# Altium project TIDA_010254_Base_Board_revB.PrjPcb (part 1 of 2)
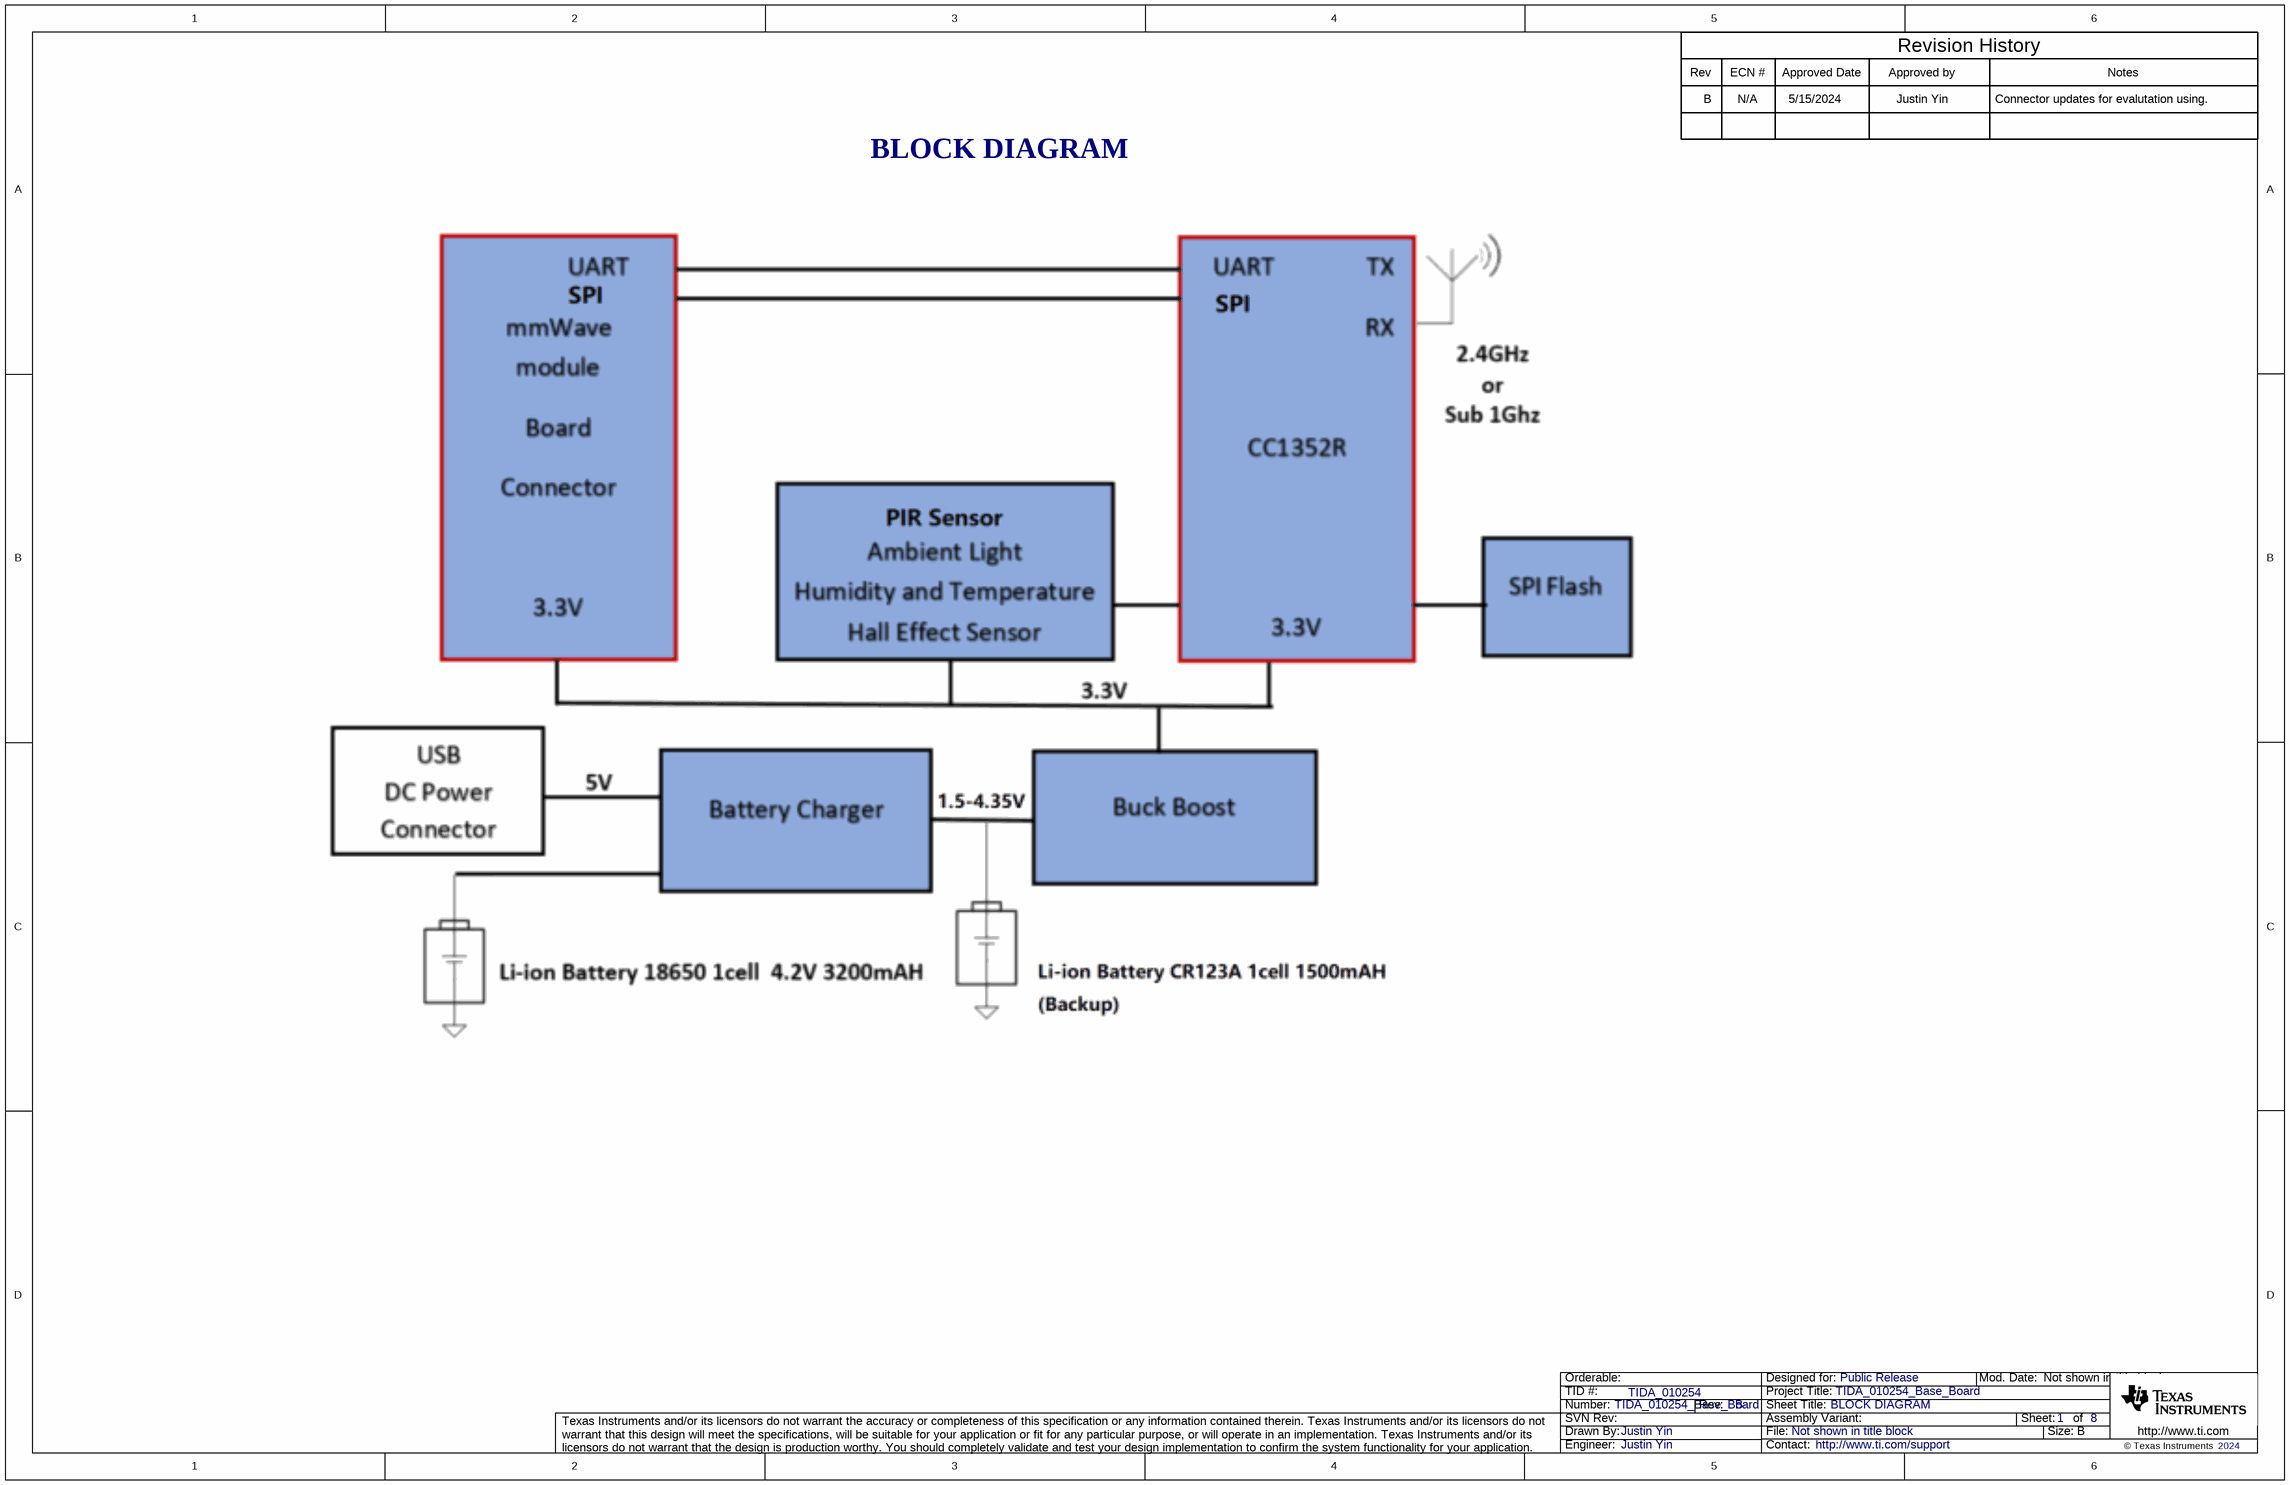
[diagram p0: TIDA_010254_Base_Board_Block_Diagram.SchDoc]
CopyrightYear: 2024; PCB_Layout: Justin Yin; PCB_Rev: B; PRJ_Customer: Public Release; PRJ_Engineer: Justin Yin; PRJ_Number: TIDA_010254_Base_Board; PRJ_Title: TIDA_010254_Base_Board; SCH_Rev: B; TechSupport: http://www.ti.com/support; TID: TIDA_010254
8 sheets, 220 parts. Net scope: flat (ports and power ports of the same name join across sheets).
Board file: TIDA_010254_Base_Board_PCB.PcbDoc
Sheets:
  TIDA_010254_Base_Board_Block_Diagram.SchDoc
  TIDA_010254_Base_Board_Table_Of_Contents.SchDoc
  TIDA_010254_Base_Board_Connector.SchDoc
  TIDA_010254_Base_Board_Charger.SchDoc
  TIDA_010254_Base_Board_DC_Regulators.SchDoc
  TIDA_010254_Base_Board_CC1352R.SchDoc
  TIDA_010254_Base_Board_Sensors.SchDoc
  TIDA_010254_Base_Board_Hardware.SchDoc

## Sheet TIDA_010254_Base_Board_Block_Diagram.SchDoc: BLOCK DIAGRAM
size 431 x 279 mm; Date: Not shown in title block; ApprovedBy: Not shown in title block; CheckedBy: Not shown in title block; Author: Not shown in title block; CompanyName: Not shown in title block; DrawnBy: Justin Yin; Organization: Not shown in title block; Address1: Not shown in title block; Address2: Not shown in title block; Address3: Not shown in title block; Address4: Not shown in title block; DocumentNumber: 1; Revision: Use project parameter SCH_Rev; SheetNumber: 1; SheetTotal: 8; PageSetup: Record=PageOptions¦CenterHorizontal=True¦CenterVertical=True¦PrintScale=1.00¦XCorrection=1.00¦YCorrection=1.00¦PrintKind=0¦BorderSize=5000000¦LeftOffset=0¦BottomOffset=0¦Orientation=2¦PaperLength=1000¦PaperWidth=1000¦Scale=100¦PaperSource=15¦PrintQuality=600¦MediaType=1¦DitherType=10¦PaperKind=Letter¦PrintScaleMode=1

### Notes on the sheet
- Rev
- B
- ECN #
- N/A
- 5/15/2024
- Approved Date
- Approved by
- Justin Yin
- Revision History
- Connector updates for evalutation using.
- Notes
- BLOCK DIAGRAM

## Sheet TIDA_010254_Base_Board_Table_Of_Contents.SchDoc: TABLE OF CONTENTS
size 431 x 279 mm; Date: Not shown in title block; ApprovedBy: Not shown in title block; CheckedBy: Not shown in title block; Author: Not shown in title block; CompanyName: Not shown in title block; DrawnBy: Justin Yin; Engineer: Not shown in title block; Organization: Not shown in title block; Address1: Not shown in title block; Address2: Not shown in title block; Address3: Not shown in title block; Address4: Not shown in title block; DocumentNumber: 2; Revision: Use project parameter SCH_Rev; SheetNumber: 2; SheetTotal: 8; PageSetup: Record=PageOptions¦CenterHorizontal=True¦CenterVertical=True¦PrintScale=1.00¦XCorrection=1.00¦YCorrection=1.00¦PrintKind=0¦BorderSize=5000000¦LeftOffset=0¦BottomOffset=0¦Orientation=2¦PaperLength=1000¦PaperWidth=1000¦Scale=100¦PaperSource=15¦PrintQuality=600¦MediaType=1¦DitherType=10¦PaperKind=Letter¦PrintScaleMode=1
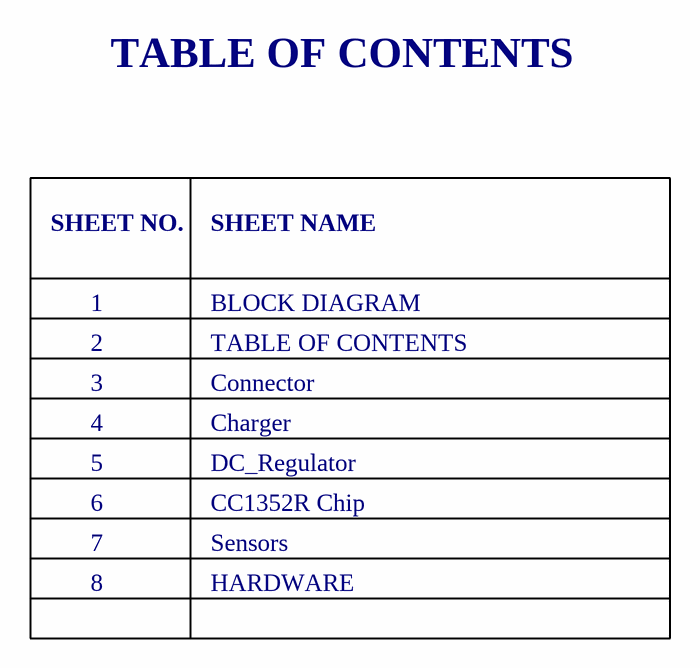
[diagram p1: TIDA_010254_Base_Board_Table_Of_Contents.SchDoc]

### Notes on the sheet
- TABLE OF CONTENTS
- SHEET NO.
- SHEET NAME
- 1
- 2
- 3
- BLOCK DIAGRAM
- Connector
- 4
- 5
- Charger
- DC_Regulator
- 7
- 8
- 6
- CC1352R Chip
- Sensors
- HARDWARE

## Sheet TIDA_010254_Base_Board_Connector.SchDoc: PWR_Connector
size 431 x 279 mm; Date: Not shown in title block; ApprovedBy: Not shown in title block; CheckedBy: Not shown in title block; Author: Not shown in title block; CompanyName: Not shown in title block; DrawnBy: Justin Yin; Engineer: Not shown in title block; Organization: Not shown in title block; Address1: Not shown in title block; Address2: Not shown in title block; Address3: Not shown in title block; Address4: Not shown in title block; DocumentNumber: 3; Revision: Use project parameter SCH_Rev; SheetNumber: 3; SheetTotal: 8; PageSetup: Record=PageOptions¦CenterHorizontal=True¦CenterVertical=True¦PrintScale=1.00¦XCorrection=1.00¦YCorrection=1.00¦PrintKind=0¦BorderSize=5000000¦LeftOffset=0¦BottomOffset=0¦Orientation=2¦PaperLength=1000¦PaperWidth=1000¦Scale=100¦PaperSource=15¦PrintQuality=600¦MediaType=1¦DitherType=10¦PaperKind=Letter¦PrintScaleMode=1
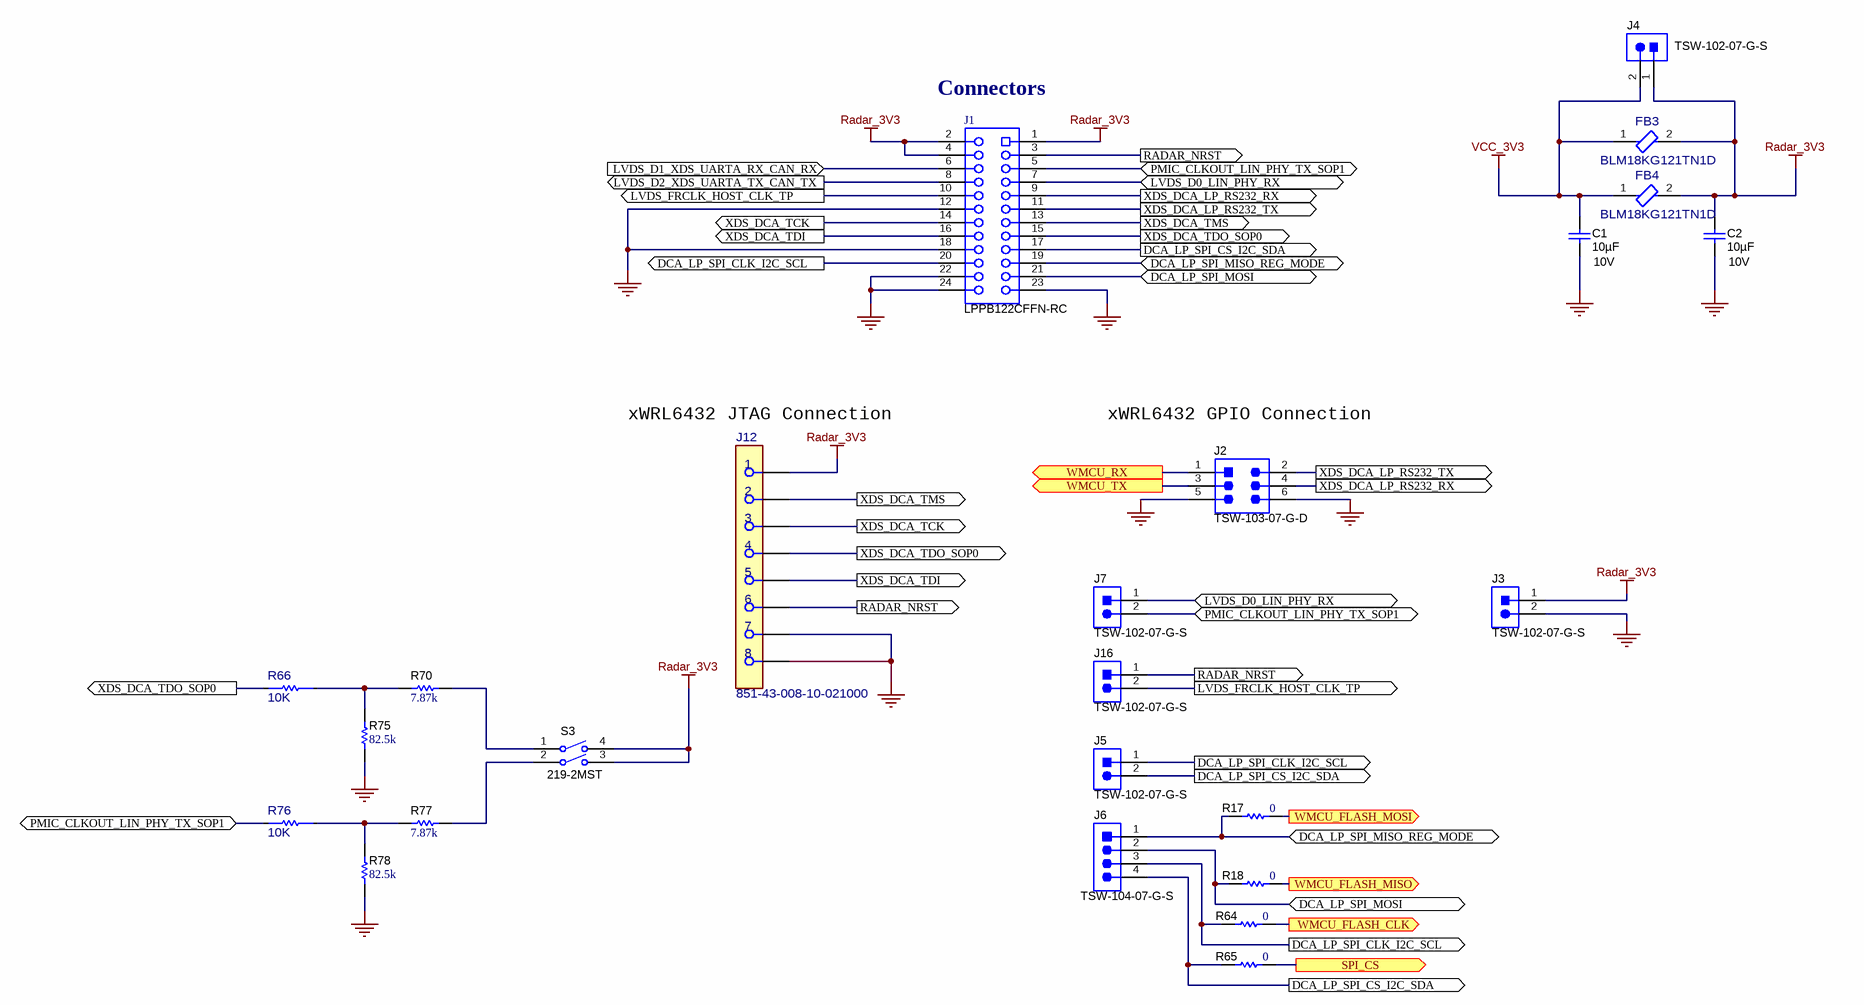
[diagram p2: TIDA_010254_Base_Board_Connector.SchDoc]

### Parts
C1  Value2: 10V  Cap_F: 10µF  [0603]  (hidden comment: GRM188Z71A106MA73D)
C2  Value2: 10V  Cap_F: 10µF  [0603]  (hidden comment: GRM188Z71A106MA73D)
FB3  BLM18KG121TN1D  [FP-BLM18KG121TN1D_0603-MFG]
FB4  BLM18KG121TN1D  [FP-BLM18KG121TN1D_0603-MFG]
J1  LPPB122CFFN-RC  [Sullins_LPPB122CFFN]
J2  TSW-103-07-G-D  [TSW-103-07-G-D]
J3  TSW-102-07-G-S  [TSW-102-07-G-S]
J4  TSW-102-07-G-S  [TSW-102-07-G-S]
J5  TSW-102-07-G-S  [TSW-102-07-G-S]
J6  TSW-104-07-G-S  [TSW-104-07-G-S]
J7  TSW-102-07-G-S  [TSW-102-07-G-S]
J12  851-43-008-10-021000  [FP-851-43-008-10-021000_HDR8-MFG]
J16  TSW-102-07-G-S  [TSW-102-07-G-S]
R17  ValueDisplayed: 0  [0402]  (hidden comment: RC0402JR-070RL)
R18  ValueDisplayed: 0  [0402]  (hidden comment: RC0402JR-070RL)
R64  ValueDisplayed: 0  [0402]  (hidden comment: RC0402JR-070RL)
R65  ValueDisplayed: 0  [0402]  (hidden comment: RC0402JR-070RL)
R66  10K  [FP-CRCW040210K0FKEDC_0402-MFG]
R70  ValueDisplayed: 7.87k  [0402]  (hidden comment: CRCW04027K87FKED)
R75  ValueDisplayed: 82.5k  [0402]  (hidden comment: CRCW040282K5FKED)
R76  10K  [FP-CRCW040210K0FKEDC_0402-MFG]
R77  ValueDisplayed: 7.87k  [0402]  (hidden comment: CRCW04027K87FKED)
R78  ValueDisplayed: 82.5k  [0402]  (hidden comment: CRCW040282K5FKED)
S3  219-2MST  [SW_219-2MST]

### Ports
DCA_LP_SPI_CLK_I2C_SCL (out), DCA_LP_SPI_CS_I2C_SDA (out), DCA_LP_SPI_MISO_REG_MODE (bidir), DCA_LP_SPI_MOSI (bidir), LVDS_D0_LIN_PHY_RX (bidir), LVDS_D1_XDS_UARTA_RX_CAN_RX (in), LVDS_D2_XDS_UARTA_TX_CAN_TX (out), LVDS_FRCLK_HOST_CLK_TP (out), PMIC_CLKOUT_LIN_PHY_TX_SOP1 (bidir), RADAR_NRST (out), SPI_CS (out), WMCU_FLASH_CLK (out), WMCU_FLASH_MISO (out), WMCU_FLASH_MOSI (out), WMCU_RX (out), WMCU_TX (out), XDS_DCA_LP_RS232_RX (out), XDS_DCA_LP_RS232_TX (out), XDS_DCA_TCK (out), XDS_DCA_TDI (out), XDS_DCA_TDO_SOP0 (out), XDS_DCA_TMS (out)

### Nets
GND: C1.2 C2.2 J1.12 J1.18 J1.22 J1.23 J1.24 J2.5 J2.6 J3.2 J12.7 J12.8 R75.1 R78.1
Radar_3V3: C2.1 FB3.2 FB4.2 J1.1 J1.2 J1.4 J3.1 J4.1 J12.1 S3.3 S3.4
VCC_3V3: C1.1 FB3.1 FB4.1 J4.2
DCA_LP_SPI_CLK_I2C_SCL: J1.20 J5.1 J6.3 R64.1 ; port DCA_LP_SPI_CLK_I2C_SCL
DCA_LP_SPI_CS_I2C_SDA: J1.17 J5.2 J6.4 R65.1 ; port DCA_LP_SPI_CS_I2C_SDA
DCA_LP_SPI_MISO_REG_MODE: J1.19 J6.1 R17.1 ; port DCA_LP_SPI_MISO_REG_MODE
DCA_LP_SPI_MOSI: J1.21 J6.2 R18.1 ; port DCA_LP_SPI_MOSI
LVDS_D0_LIN_PHY_RX: J1.7 J7.1 ; port LVDS_D0_LIN_PHY_RX
LVDS_D1_XDS_UARTA_RX_CAN_RX: J1.6 ; port LVDS_D1_XDS_UARTA_RX_CAN_RX
LVDS_D2_XDS_UARTA_TX_CAN_TX: J1.8 ; port LVDS_D2_XDS_UARTA_TX_CAN_TX
LVDS_FRCLK_HOST_CLK_TP: J1.10 J16.2 ; port LVDS_FRCLK_HOST_CLK_TP
PMIC_CLKOUT_LIN_PHY_TX_SOP1: J1.5 J7.2 R76.2 ; port PMIC_CLKOUT_LIN_PHY_TX_SOP1
RADAR_NRST: J1.3 J12.6 J16.1 ; port RADAR_NRST
SPI_CS: R65.2 ; port SPI_CS
WMCU_FLASH_CLK: R64.2 ; port WMCU_FLASH_CLK
WMCU_FLASH_MISO: R18.2 ; port WMCU_FLASH_MISO
WMCU_FLASH_MOSI: R17.2 ; port WMCU_FLASH_MOSI
WMCU_RX: J2.1 ; port WMCU_RX
WMCU_TX: J2.3 ; port WMCU_TX
XDS_DCA_LP_RS232_RX: J1.9 J2.4 ; port XDS_DCA_LP_RS232_RX
XDS_DCA_LP_RS232_TX: J1.11 J2.2 ; port XDS_DCA_LP_RS232_TX
XDS_DCA_TCK: J1.14 J12.3 ; port XDS_DCA_TCK
XDS_DCA_TDI: J1.16 J12.5 ; port XDS_DCA_TDI
XDS_DCA_TDO_SOP0: J1.15 J12.4 R66.2 ; port XDS_DCA_TDO_SOP0
XDS_DCA_TMS: J1.13 J12.2 ; port XDS_DCA_TMS
NetR66_1: R66.1 R70.1 R75.2
NetR70_2: R70.2 S3.1
NetR76_1: R76.1 R77.1 R78.2
NetR77_2: R77.2 S3.2

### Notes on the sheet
- (near J1) Connectors
- (near J12) xWRL6432 JTAG Connection
- (near J2) xWRL6432 GPIO Connection

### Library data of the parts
C1 C2 = CMP-0007497-5: CAP, CERM, 10 uF, 10 V, +/- 20%, X7R, 0603; Manufacturer: MuRata; TaMin_C: -55°C; Polarized: N; SizeAreaWB_mm2: 4.68; Value1: Unknown; U/M: EA; Value: 10uF; TaMax_C: 125°C; SizeZ_mm: 1; SizeX_mm: 1.6; SizeY_mm: 0.8; SizeArea_mm2: 1.28; AEC Category: Q200
FB3 FB4 = CMP-0089995-1: 120 Ohms @ 100MHz 1 Power Line Ferrite Bead 0603 (1608 Metric) 3A 30mOhm; Manufacturer: Murata; DCR_ohm: 30m; Impedance At Frequency: 120Ω @ 100MHz; Tolerance_%: 25%; AEC Qualified: No; SizeZ_mm: 0.75mm
J1 = CMP-0067662-1: Receptacle, 1.27mm, 12x2, Gold, TH; Manufacturer: Sullins Connector Solutions; CNHeader: False; Current_A: 1A; Gender: Female; Voltage_V: 500V; CompType: Socket Strip; Row_Count: 2; RowSpacing_mm: 1.27; CT: True; Cert_UL: Y
J2 = CMP-0075406-2: Header, 100mil, 3x2, Gold, TH; Manufacturer: Samtec; Pitch_mm: 2.54; Cert_VDE: N; Gender: Male; Cert_CSA: Y; Voltage_V: 550V; Green_REACh: Passed; Current_A: 6.3A; Green_Lifecycle: Active; Row_Count: 2
J3-J5 J7 J16 = CMP-0075405-3: Header, 100mil, 2x1, Gold, TH; Manufacturer: Samtec; Current_A: 6.3A; Green_Lifecycle: Active; Pitch_mm: 2.54; Cert_CSA: Y; Cert_VDE: N; Green_REACh: Passed; Row_Count: 1; Gender: Male; Voltage_V: 550V
J6 = CMP-0075409-2: Header, 100mil, 4x1, Gold, TH; Manufacturer: Samtec; Pitch_mm: 2.54; Cert_VDE: N; Gender: Male; Cert_CSA: Y; Voltage_V: 550V; Green_REACh: Passed; Current_A: 6.3A; Green_Lifecycle: Active; Row_Count: 1
J12 = CMP-0092742-1: 8 Position Receptacle Connector 0.050" (1.27mm) Through Hole Gold; Manufacturer: Mill-Max; Is Female: yes; Row_Count: 1; AEC Qualified: No; ContactFinish: Gold,Nickel; Conn Gender: Female; Current_A: 3A; Conn Orientation: Vertical; SizeZ_mm: 0.161inch
R17 R18 R64 R65 = CMP-0027004-2: RES, 0, 5%, 0.063 W, 0402; Manufacturer: Yageo America; Power_W: 63mW; TempCo: 200 ppm/C; Value_Code: 0000; U/M: EA; Value: 0; EIA_Code: E24; SizeX_mm: 1; SizeY_mm: 0.5; SizeZ_mm: 0.6; Value2: 0.063W; VDC_V: 50V; AEC Category: Q200
R66 R76 = CMP-0094735-1: 10 kOhms ±1% 0.063W, 1/16W Chip Resistor 0402 (1005 Metric)  Thick Film; PartNumber: CRCW040210K0FKEDC; Manufacturer: Vishay; SizeZ_mm: 0.4mm; Power_W: 63mW; VDC_V: 50V; AEC Grade: Grade 0; TempCo: 100ppm/°C; AEC Qualified: Yes
R70 R77 = CMP-0026557-2: RES, 7.87 k, 1%, 0.063 W, AEC-Q200 Grade 0, 0402; Manufacturer: Vishay-Dale; Power_W: 63mW; TempCo: 100 ppm/C; Value_Code: 7k87; Value: 7.87k; EIA_Code: E96; SizeX_mm: 1; SizeY_mm: 0.5; SizeZ_mm: 0.6; Value2: 0.063W; AEC Qualified: Y; VDC_V: 50V; AEC Grade: 0; AEC Category: Q200
R75 R78 = CMP-0026574-2: RES, 82.5 k, 1%, 0.063 W, AEC-Q200 Grade 0, 0402; Manufacturer: Vishay-Dale; Power_W: 63mW; TempCo: 100 ppm/C; Value_Code: 82k5; Value: 82.5k; EIA_Code: E96; SizeX_mm: 1; SizeY_mm: 0.5; SizeZ_mm: 0.6; Value2: 0.063W; AEC Qualified: Y; VDC_V: 50V; AEC Grade: 0; AEC Category: Q200
S3 = CMP-0002290-1: Switch, SPST, Slide, Off-On, 2 Pos, 0.1A, 20V, SMD; Manufacturer: CTS Electrocomponents; CurrentRating_mA: 100A; PositionCount: 2; SizeX_mm: 9.91; SizeY_mm: 6.55; SizeZ_mm: 4.23; SizeArea_mm2: 64.9105; SizeAreaWB_mm2: 101.8305

## Sheet TIDA_010254_Base_Board_Charger.SchDoc: Charger
size 431 x 279 mm; Date: Not shown in title block; ApprovedBy: Not shown in title block; CheckedBy: Not shown in title block; Author: Not shown in title block; CompanyName: Not shown in title block; DrawnBy: Justin Yin; Engineer: Not shown in title block; Organization: Not shown in title block; Address1: Not shown in title block; Address2: Not shown in title block; Address3: Not shown in title block; Address4: Not shown in title block; DocumentNumber: 4; Revision: Use project parameter SCH_Rev; SheetNumber: 4; SheetTotal: 8; PageSetup: Record=PageOptions¦CenterHorizontal=True¦CenterVertical=True¦PrintScale=1.00¦XCorrection=1.00¦YCorrection=1.00¦PrintKind=0¦BorderSize=5000000¦LeftOffset=0¦BottomOffset=0¦Orientation=2¦PaperLength=1000¦PaperWidth=1000¦Scale=100¦PaperSource=15¦PrintQuality=600¦MediaType=1¦DitherType=10¦PaperKind=Letter¦PrintScaleMode=1
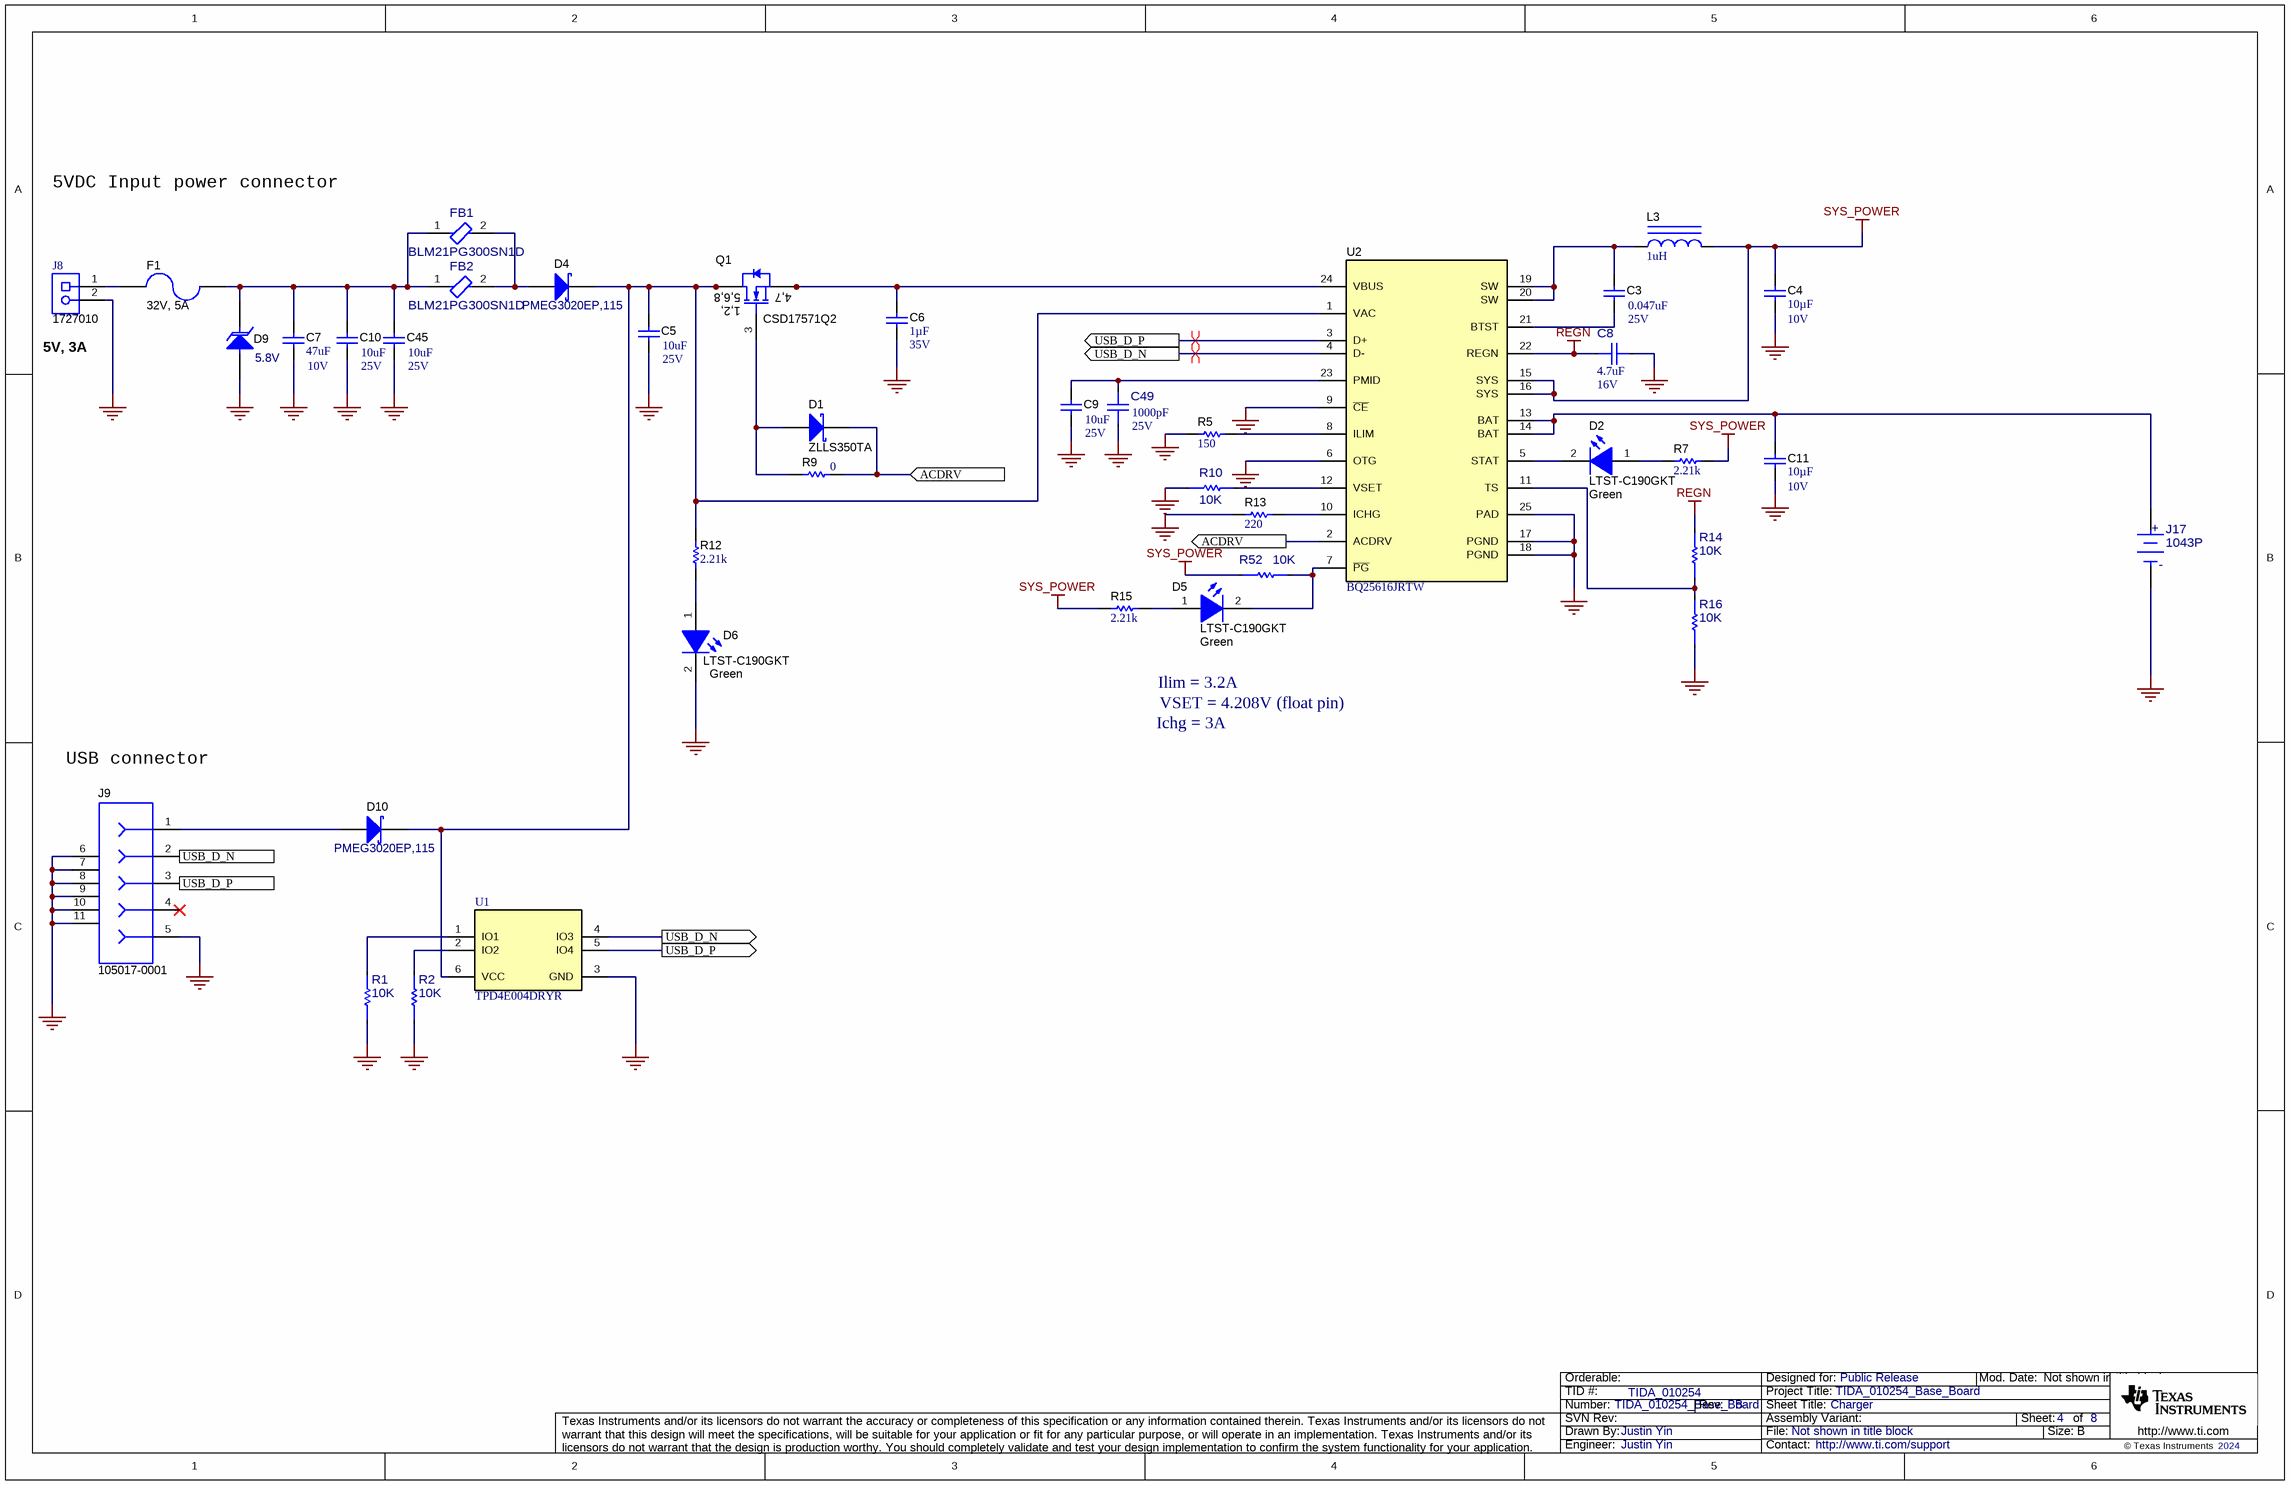
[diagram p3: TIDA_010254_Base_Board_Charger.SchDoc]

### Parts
C3  VDC_V: 25V  ValueDisplayed: 0.047uF  [0402]  (hidden comment: GRM155R71E473KA88D)
C4  Cap_F: 10µF  VDC_V: 10V  [0805_HV]  (hidden comment: GRM21BR71A106KA73L)
C5  VDC_V: 25V  ValueDisplayed: 10uF  [0805_HV]  (hidden comment: GRM21BR61E106KA73L)
C6  Cap_F: 1µF  VDC_V: 35V  [0603]  (hidden comment: C1608X7R1V105K080AC)
C7  Value2: 10V  ValueDisplayed: 47uF  [1206_180]  (hidden comment: GRM31CR61A476KE15L)
C8  ValueDisplayed: 4.7uF  VDC_V: 16V  [FP-GRM188R61C475KE11D_0603-MFG]  (hidden comment: GRM188R61C475KE11D)
C9  VDC_V: 25V  ValueDisplayed: 10uF  [0805_HV]  (hidden comment: GRM21BR61E106KA73L)
C10  VDC_V: 25V  ValueDisplayed: 10uF  [0805_HV]  (hidden comment: GRM21BR61E106KA73L)
C11  Cap_F: 10µF  VDC_V: 10V  [0805_HV]  (hidden comment: GRM21BR71A106KA73L)
C45  VDC_V: 25V  ValueDisplayed: 10uF  [0805_HV]  (hidden comment: GRM21BR61E106KA73L)
C49  VDC_V: 25V  ValueDisplayed: 1000pF  [FP-GRM033R61E102KA01D_0201-MFG]  (hidden comment: GRM033R61E102KA01D)
D1  ZLLS350TA  [SOD-523]
D2  LTST-C190GKT  value Green  [LED_LTST-C190]
D4  PMEG3020EP,115  [SOD-128]
D5  LTST-C190GKT  value Green  [LED_LTST-C190]
D6  LTST-C190GKT  value Green  [LED_LTST-C190]
D9  value 5.8V  [SMB]  (hidden comment: SZP6SMB6.8AT3G)
D10  PMEG3020EP,115  [SOD-128]
F1  32V, 5A  [1206]
FB1  BLM21PG300SN1D  [FP-BLM21PG300SN1D_0805-MFG]
FB2  BLM21PG300SN1D  [FP-BLM21PG300SN1D_0805-MFG]
J8  1727010  [PhoenixConact_1727010]
J9  105017-0001  [CONN_105017-0001]
J17  1043P  [FP-1043P_BATT_HOLDER_18650-MFG]
L3  ValueDisplayed: 1uH  [WE-SPC_4838]  (hidden comment: 74408943010)
Q1  CSD17571Q2  [DQK0006C]
R1  10K  [FP-CRCW040210K0FKEDC_0402-MFG]
R2  10K  [FP-CRCW040210K0FKEDC_0402-MFG]
R5  ValueDisplayed: 150  [0402]  (hidden comment: CRCW0402150RFKED)
R7  ValueDisplayed: 2.21k  [0402]  (hidden comment: CRCW04022K21FKED)
R9  ValueDisplayed: 0  [0402]  (hidden comment: RC0402JR-070RL)
R10  10K  [FP-CRCW040210K0FKEDC_0402-MFG]
R12  ValueDisplayed: 2.21k  [0402]  (hidden comment: CRCW04022K21FKED)
R13  ValueDisplayed: 220  [0402]  (hidden comment: ERJ-2RKF2200X)
R14  10K  [FP-CRCW040210K0FKEDC_0402-MFG]
R15  ValueDisplayed: 2.21k  [0402]  (hidden comment: CRCW04022K21FKED)
R16  10K  [FP-CRCW040210K0FKEDC_0402-MFG]
R52  10K  [FP-CRCW040210K0FKEDC_0402-MFG]
U1  TPD4E004DRYR  [DRY0006A]
U2  BQ25616JRTW  [RTW0024P]

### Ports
ACDRV (in), ACDRV (out), USB_D_N (out), USB_D_P (out)

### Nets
GND: C4.2 C5.2 C6.2 C7.2 C8.2 C9.2 C10.2 C11.2 C45.2 C49.1 D6.2(K) D9.2(A) J8.2 J9.5 J9.6 J9.7 J9.8 J9.9 J9.10 J9.11 J17.1(CATHODE) R1.1 R2.1 R5.1 R10.1 R13.1 R16.1 U1.3(GND) U2.6(OTG) U2.9(~{CE}) U2.17(PGND) U2.18(PGND) U2.25(PAD)
REGN: C8.1 R14.2 U2.22(REGN)
SYS_POWER: C4.1 L3.2 R7.1 R15.2 R52.1 U2.15(SYS) U2.16(SYS)
ACDRV: D1.1(K) R9.2 U2.2(ACDRV) ; port ACDRV
USB_D_N: J9.2 U1.4(IO3) U2.4(D-) ; port USB_D_N
USB_D_P: J9.3 U1.5(IO4) U2.3(D+) ; port USB_D_P
NetC3_1: C3.1 L3.1 U2.19(SW) U2.20(SW)
NetC3_2: C3.2 U2.21(BTST)
NetC5_1: C5.1 D4.1(K) D10.1(K) Q1.1(D) Q1.2(D) Q1.5(D) Q1.6(D) Q1.8(D) R12.1 U1.6(VCC) U2.1(VAC)
NetC6_1: C6.1 Q1.4(S) Q1.7(S) U2.24(VBUS)
NetC7_1: C7.1 C10.1 C45.1 D9.1(K) F1.1 FB1.1 FB2.1
NetC9_1: C9.1 C49.2 U2.23(PMID)
NetC11_1: C11.1 J17.2(ANODE) U2.13(BAT) U2.14(BAT)
NetD1_2: D1.2(A) Q1.3(G) R9.1
NetD2_1: D2.1(A) R7.2
NetD2_2: D2.2(K) U2.5(STAT)
NetD4_2: D4.2(A) FB1.2 FB2.2
NetD5_1: D5.1(A) R15.1
NetD5_2: D5.2(K) R52.2 U2.7(~{PG})
NetD6_1: D6.1(A) R12.2
NetD10_2: D10.2(A) J9.1
NetF1_2: F1.2 J8.1
NetR1_2: R1.2 U1.1(IO1)
NetR2_2: R2.2 U1.2(IO2)
NetR5_2: R5.2 U2.8(ILIM)
NetR10_2: R10.2 U2.12(VSET)
NetR13_2: R13.2 U2.10(ICHG)
NetR14_1: R14.1 R16.2 U2.11(TS)

Not connected (* = marked no-connect by the designer): J9 4*

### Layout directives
differential pair; rule Differential Pairs Routing [Pref Gap = 5.2mil    Min Gap  = 5.2mil    Max Gap  = 5.2milPref Width = 5.8mil    Min Width  = 5.8mil    Max Width  = 5.8mil]: USB_D_N, USB_D_P

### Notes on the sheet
- 5VDC Input power connector
- (near J8) 5V, 3A
- Ilim = 3.2A
- VSET = 4.208V (float pin)
- USB connector
- Ichg = 3A

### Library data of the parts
C3 = CMP-0006669-2: CAP, CERM, 0.047 uF, 25 V, +/- 10%, X7R, 0402; Manufacturer: MuRata; TaMin_C: -55°C; Polarized: N; SizeAreaWB_mm2: 3; Value1: Unknown; U/M: EA; TaMax_C: 125°C; SizeZ_mm: 0.6; SizeX_mm: 1; SizeY_mm: 0.5; Cap_F: 47nF; AEC Category: Q200
C4 C11 = CMP-0081849-1: CAP, CERM, 10 µF,  V,+/- 10%, X7R, 0805; Manufacturer: MuRata; TaMin_C: -55°C; Polarized: N; Green_Lifecycle: Active; SizeAreaWB_mm2: 6.75; Green_REACh: Passed; U/M: EA; Value: 10uF; TaMax_C: 125°C; SizeZ_mm: 1.45; SizeX_mm: 2; SizeY_mm: 1.25; Cap_Case: 0805; SizeArea_mm2: 2.5; AEC Category: Q200
C5 C9 C10 C45 = CMP-0008302-2: CAP, CERM, 10 uF, 25 V, +/- 10%, X5R, 0805; Manufacturer: MuRata; TaMin_C: -55°C; Polarized: N; SizeAreaWB_mm2: 6.75; Value1: Unknown; U/M: EA; Value: 10uF; TaMax_C: 85°C; SizeZ_mm: 1.45; SizeX_mm: 2; SizeY_mm: 1.25; Cap_Case: 0805; SizeArea_mm2: 2.5; Cap_F: 10µF; AEC Category: Q200
C6 = CMP-0007052-4: CAP, CERM, 1 uF, 35 V, +/- 10%, X7R, 0603; Manufacturer: TDK; TaMin_C: -55°C; Polarized: N; SizeAreaWB_mm2: 4.68; Value1: Unknown; U/M: EA; Value: 1uF; TaMax_C: 125°C; SizeZ_mm: 1; SizeX_mm: 1.6; SizeY_mm: 0.8; SizeArea_mm2: 1.28; AEC Category: Q200
C7 = CMP-0008944-2: CAP, CERM, 47 uF, 10 V, +/- 10%, X5R, 1206; Manufacturer: MuRata; TaMin_C: -55°C; Polarized: N; SizeAreaWB_mm2: 10.92; Value1: Unknown; U/M: EA; Value: 47uF; TaMax_C: 85°C; SizeZ_mm: 1.8; SizeX_mm: 3.2; SizeY_mm: 1.6; Cap_Case: 1206; SizeArea_mm2: 5.12; Cap_F: 47µF; AEC Category: Q200
C8 = CMP-0098153-1: Chip Multilayer Ceramic Capacitors for General Purpose, 0603, 4.7uF, X5R, 15%, 10%, 16V; Manufacturer: Murata; SizeZ_mm: 0.95mm; Cap_F: 4.7µF; Value: 4.7µF; AEC Qualified: No
C49 = CMP-0098152-1: Chip Multilayer Ceramic Capacitors for General Purpose, 0201, 1000pF, X5R, 15%, 10%, 25V; Manufacturer: Murata; SizeZ_mm: 0.33mm; Cap_F: 1nF; Value: 1nF; AEC Qualified: No
D1 = CMP-0028378-3: Diode, Schottky, 40 V, 0.38 A, SOD-523; Manufacturer: Diodes Inc.; Value1: 0.38A; Value2: 0.79V; Green_Lifecycle: Active; SizeArea_mm2: 1.53; Vf_V: 790mV; AEC Category: Q101; SizeZ_mm: 0.65; Io_A: 380mA; SizeY_mm: 0.9; SizeAreaWB_mm2: 5.13; Green_REACh: Passed; SizeX_mm: 1.7; Vr_V: 40V; Value: 40V
D2 D5 D6 = CMP-0002827-3: LED, Green, SMD; Manufacturer: Lite-On; Power_TotalModule: 100mW; Value2: 2.1V; Io_A: 20mA; Value1: 0.1W
D4 D10 = CMP-0078758-2: Diode, Schottky, 30 V, 2 A, AEC-Q101, SOD-128; Manufacturer: Nexperia; Value2: 0.36V; SizeAreaWB_mm2: 19.6; Io_A: 2A; Value: 30V; AEC Qualified: Y; TJmax_C: 150°C; SizeX_mm: 4.6; AEC Category: Q101; SizeY_mm: 2.5; SizeArea_mm2: 11.5; Vf_V: 3.6dV; SizeZ_mm: 1.1
D9 = CMP-0078243-3: Diode, TVS, Uni, 5.8 V, 10.5 Vc, AEC-Q101, SMB; Manufacturer: Littelfuse; SizeAreaWB_mm2: 44.156; Value1: 0.55W; RJA_CperW: 226; SizeZ_mm: 2.6; SizeX_mm: 5.6; SizeY_mm: 3.81; SizeArea_mm2: 21.336; AEC Qualified: Y; AEC Category: Q101; Vc: 10.5V
F1 = CMP-0003458-2: Fuse, 5 A, 32VAC/VDC, SMD; Manufacturer: Littelfuse; PartNumber: 0440005.WR; SizeAreaWB_mm2: 10.92; Interrupt_AC: 50A; SizeZ_mm: 1.35; SizeX_mm: 3.2; SizeY_mm: 1.6; SizeArea_mm2: 5.12; Rtyp_Ohm: 0.012; MeltingTyp: 4.761
FB1 FB2 = CMP-0098084-1: Chip Ferrite Bead, 0805, 30Ω @ 100MHz, 0.014Ω, , 4A; Manufacturer: Murata; Ciiva Ids: 886678; DCR_ohm: 14m; Import Ts: 1521843479; AEC Qualified: No; SizeZ_mm: 1.05mm
J8 = CMP-0055472-1: Conn Term Block, 2POS, 3.81mm, TH; Manufacturer: Phoenix Contact; CT: TRUE; Green_REACh: Incomplete; CompType: Terminal Block; CNHeader: FALSE; Green_Lifecycle: Not Set
J9 = CMP-0055293-1: Connector, Receptacle, Micro-USB Type B, R/A, Bottom Mount SMT; Manufacturer: Molex; CNHeader: FALSE; Green_Lifecycle: Active; Gender: Female; Green_REACh: Passed; CompType: USB; CT: TRUE
J17 = CMP-0097895-1: Battery Holder (Open) 18650 1 Cell PC Pin; Manufacturer: Keystone; Conn Orientation: Vertical; AEC Qualified: No; SizeZ_mm: 15.11mm; ContactFinish: Tin,Nickel
L3 = CMP-0063878-1: Inductor, Shielded Drum Core, Ferrite, 1 uH, 3.3 A, 0.019 ohm, SMD; Manufacturer: Wurth Elektronik; Isat: 6.5A @ 35% inductance drop; Irms: 3.3A @ 40C rise; Green_Lifecycle: Active; SizeAreaWB_mm2: 33.64; DCR_ohm: 0.019; Green_REACh: Passed; Value: 1uH; Imax_A: 3.3A; SizeZ_mm: 4.1; SizeX_mm: 4.8; SizeArea_mm2: 23.04; Ind_H: 1µH; AEC Category: Q200
Q1 = CMP-0000585-1: MOSFET, N-CH, 30 V, 22 A, DQK0006C (WSON-6); Alternate Manufacturer: None; Manufacturer: Texas Instruments; SizeZ_mm: 0.8; ChType: N; Value2: 2.4 nC; Value1: 0.02; VdsMax_V: 30V; SizeX_mm: 2; Vgs_V: 20V; Value: 30V; Rdson45_ohm: 0.029; SizeArea_mm2: 4; AEC Category: Q101; IdsMax_A: 22A; SizeAreaWB_mm2: 9; U/M: EA; QgTyp_nC: 2.4
R1 R2 R10 R14 R16 R52 = CMP-0094735-1: as R66 on sheet TIDA_010254_Base_Board_Connector
R5 = CMP-0026022-3: RES, 150, 1%, 0.063 W, AEC-Q200 Grade 0, 0402; Manufacturer: Vishay-Dale; Power_W: 63mW; TempCo: 100 ppm/C; Value_Code: 150R; Value: 150; EIA_Code: E96; SizeX_mm: 1; SizeY_mm: 0.5; SizeZ_mm: 0.6; Value2: 0.063W; AEC Qualified: Y; VDC_V: 50V; AEC Category: Q200; AEC Grade: 0
R7 R12 R15 = CMP-0026232-2: RES, 2.21 k, 1%, 0.063 W, AEC-Q200 Grade 0, 0402; Manufacturer: Vishay-Dale; Power_W: 63mW; TempCo: 100 ppm/C; Value_Code: 2k21; Value: 2.21k; EIA_Code: E96; SizeX_mm: 1; SizeY_mm: 0.5; SizeZ_mm: 0.6; Value2: 0.063W; AEC Qualified: Y; VDC_V: 50V; AEC Category: Q200; AEC Grade: 0
R9 = CMP-0027004-2: as R17 on sheet TIDA_010254_Base_Board_Connector
R13 = CMP-0026680-1: RES, 220, 1%, 0.1 W, AEC-Q200 Grade 0, 0402; Manufacturer: Panasonic; Power_W: 100mW; TempCo: 100 ppm/C; Value_Code: 220R; U/M: EA; Value: 220; SizeX_mm: 1; SizeY_mm: 0.5; SizeZ_mm: 0.6; Value2: 0.1W; AEC Qualified: Y; VDC_V: 50V; AEC Grade: 0; AEC Category: Q200
U1 = CMP-0043115-3: 4-Channel ESD Protection Array for High-Speed Data Interfaces, DRY0006A (USON-6); Manufacturer: Texas Instruments; IO Leakage Current(nA): 1; USB High Speed: TRUE; IO Capacitance(Typ)(pF): 1.6; Eco-Plan: Green (RoHS & no Sb/Br); IEC 61000-4-2 Contact(+/- kV): 8; Breakdown Voltage(Min)(V): 6; IEC 61000-4-2 Air-Gap(+/- kV): 12; AEC Category: Q200; AEC Qualified: N; CompType: IC; SizeAreaWB_mm2: 4.9; SizeArea_mm2: 1.45; SizeX_mm: 1.0; SizeZ_mm: 0.6; Rating: Catalog
U2 = CMP-0860206-1: BQ25616JRTW, RTW0024P (PVQFN-24); Alternate Manufacturer: Texas Instruments; SizeY_mm: 4; AEC Qualified: N; SizeArea_mm2: 16; AEC Category: Q200; SizeAreaWB_mm2: 25; CompType: IC; SizeZ_mm: 0.8

## Sheet TIDA_010254_Base_Board_DC_Regulators.SchDoc: DC_REGULATOR
size 431 x 279 mm; Date: Not shown in title block; ApprovedBy: Not shown in title block; CheckedBy: Not shown in title block; Author: Not shown in title block; CompanyName: Not shown in title block; DrawnBy: Justin Yin; Engineer: Not shown in title block; Organization: Not shown in title block; Address1: Not shown in title block; Address2: Not shown in title block; Address3: Not shown in title block; Address4: Not shown in title block; DocumentNumber: 5; Revision: Use project parameter SCH_Rev; SheetNumber: 5; SheetTotal: 8; PageSetup: Record=PageOptions¦CenterHorizontal=True¦CenterVertical=True¦PrintScale=1.00¦XCorrection=1.00¦YCorrection=1.00¦PrintKind=0¦BorderSize=5000000¦LeftOffset=0¦BottomOffset=0¦Orientation=2¦PaperLength=1000¦PaperWidth=1000¦Scale=100¦PaperSource=15¦PrintQuality=600¦MediaType=1¦DitherType=10¦PaperKind=Letter¦PrintScaleMode=1
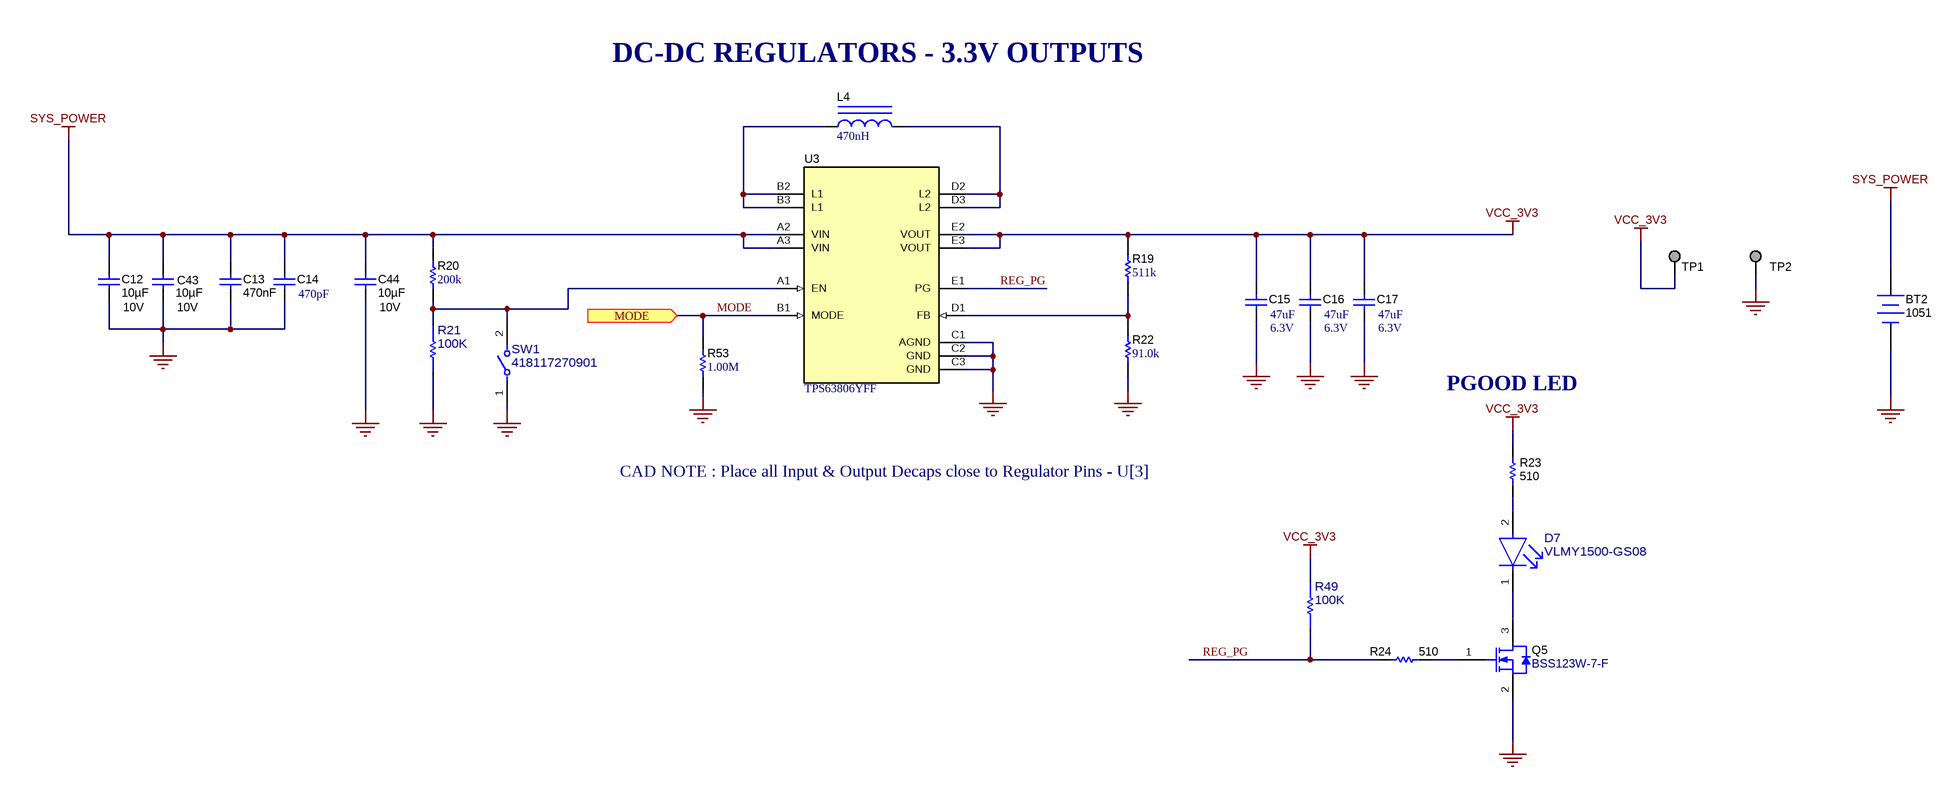
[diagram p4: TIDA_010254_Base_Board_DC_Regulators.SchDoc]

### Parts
BT2  1051  [Keystone_1051]
C12  Value2: 10V  Cap_F: 10µF  [0603]  (hidden comment: GRM188Z71A106MA73D)
C13  Cap_F: 470nF  [0603L]  (hidden comment: GRM188R71C474KA88D)
C14  ValueDisplayed: 470pF  [0402L]  (hidden comment: GRM1555C1H471JA01D)
C15  VDC_V: 6.3V  ValueDisplayed: 47uF  [0603]  (hidden comment: GRM188R60J476ME15D)
C16  VDC_V: 6.3V  ValueDisplayed: 47uF  [0603]  (hidden comment: GRM188R60J476ME15D)
C17  VDC_V: 6.3V  ValueDisplayed: 47uF  [0603]  (hidden comment: GRM188R60J476ME15D)
C43  Value2: 10V  Cap_F: 10µF  [0603]  (hidden comment: GRM188Z71A106MA73D)
C44  Value2: 10V  Cap_F: 10µF  [0603]  (hidden comment: GRM188Z71A106MA73D)
D7  VLMY1500-GS08  [FP-VLMY1500-GS08_0402-MFG]
L4  ValueDisplayed: 470nH  [XFL4015]  (hidden comment: XFL4015-471MEC)
Q5  BSS123W-7-F  [SOT-323]
R19  ValueDisplayed: 511k  [0402]  (hidden comment: CRCW0402511KFKED)
R20  ValueDisplayed: 200k  [0402]  (hidden comment: CRCW0402200KFKED)
R21  100K  [FP-RC0402JR-07100KL_0402-MFG]
R22  ValueDisplayed: 91.0k  [RC0402]  (hidden comment: RC0402FR-0791KL)
R23  ValueDisplayed: 510  [0402L]  (hidden comment: ERJ-2GEJ511X)
R24  ValueDisplayed: 510  [0402L]  (hidden comment: ERJ-2GEJ511X)
R49  100K  [FP-RC0402JR-07100KL_0402-MFG]
R53  ValueDisplayed: 1.00M  [0402]  (hidden comment: RMCF0402FT1M00)
SW1  418117270901  [FP-418117270901_DIP_SW1-MFG]
TP1  TESTPOINT  [TP_25MIL-SMT]  (value not drawn)  (no BOM)
TP2  TESTPOINT  [TP_25MIL-SMT]  (value not drawn)  (no BOM)
U3  TPS63806YFF  [YFF0015AHAN]

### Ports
MODE (in)

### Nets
GND: BT2.2(-) C12.2 C13.2 C14.2 C15.2 C16.2 C17.2 C43.2 C44.2 Q5.2(S) R21.2 R22.1 R53.1 SW1.1 TP2.1 U3.C1(AGND) U3.C2(GND) U3.C3(GND)
SYS_POWER: BT2.1(+) C12.1 C13.1 C14.1 C43.1 C44.1 R20.2 U3.A2(VIN) U3.A3(VIN)
VCC_3V3: C15.1 C16.1 C17.1 R19.2 R23.2 R49.1 TP1.1 U3.E2(VOUT) U3.E3(VOUT)
MODE: R53.2 U3.B1(MODE) ; port MODE
REG_PG: R24.1 R49.2 U3.E1(PG)
NetD7_1: D7.1(CATHODE) Q5.3(D)
NetD7_2: D7.2(ANODE) R23.1
NetL4_1: L4.1 U3.B2(L1) U3.B3(L1)
NetL4_2: L4.2 U3.D2(L2) U3.D3(L2)
NetQ5_1: Q5.1(G) R24.2
NetR19_1: R19.1 R22.2 U3.D1(FB)
NetR20_1: R20.1 R21.1 SW1.2 U3.A1(EN)

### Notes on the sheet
- DC-DC REGULATORS - 3.3V OUTPUTS
- PGOOD LED
- CAD NOTE : Place all Input & Output Decaps close to Regulator Pins - U[3]

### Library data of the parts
BT2 = CMP-0003704-1: Battery Holder, CR123A, TH; Manufacturer: Keystone
C12 C43 C44 = CMP-0007497-5: as C1 on sheet TIDA_010254_Base_Board_Connector
C13 = CMP-0007398-4: CAP, CERM, 0.47 uF, 16 V, +/- 10%, X7R, 0603; Manufacturer: MuRata; TaMin_C: -55°C; Polarized: N; SizeAreaWB_mm2: 4.68; Value1: Unknown; U/M: EA; Value: 0.47uF; TaMax_C: 125°C; SizeZ_mm: 1; SizeX_mm: 1.6; SizeY_mm: 0.8; Cap_Case: 0603; Value2: 16V; SizeArea_mm2: 1.28; AEC Category: Q200
C14 = CMP-0006470-2: CAP, CERM, 470 pF, 50 V, +/- 5%, C0G/NP0, 0402; Manufacturer: MuRata; TaMin_C: -55°C; Polarized: N; SizeAreaWB_mm2: 3; Value1: Unknown; U/M: EA; Value: 470pF; TaMax_C: 125°C; SizeZ_mm: 0.6; SizeX_mm: 1; SizeY_mm: 0.5; Cap_Case: 0402; Value2: 50V; AEC Category: Q200
C15-C17 = CMP-0007313-5: CAP, CERM, 47 uF, 6.3 V, +/- 20%, X5R, 0603; Manufacturer: MuRata; TaMin_C: -55°C; Polarized: N; SizeAreaWB_mm2: 4.68; Value1: Unknown; U/M: EA; Value: 47uF; TaMax_C: 85°C; SizeZ_mm: 1; SizeX_mm: 1.6; SizeY_mm: 0.8; SizeArea_mm2: 1.28; Cap_F: 47µF; AEC Category: Q200
D7 = CMP-0090807-1: LED Uni-Color Yellow 588nm 2-Pin Chip 0402(1006Metric) T/R; Manufacturer: Vishay; AEC Qualified: No; Led Orientation: Top View; SizeZ_mm: 0.35mm; TaMin_C: -30°C; Angle: 130°; LambdaD: 590nm; Power_TotalModule: 75mW; TaMax_C: +85°C; Forward Current: 20mA; Vr_V: 5V; Vf_V: 2V; Luminous Intensity: 90mcd
L4 = CMP-0061147-1: Inductor, Shielded, Composite, 470 nH, 3.5 A, 0.0076 ohm, SMD; Manufacturer: Coilcraft; Isat: 3.5A @ 10% inductance drop; Irms: 9.1A @ 20C rise; Green_Lifecycle: Not Set; SizeAreaWB_mm2: 28.09; DCR_ohm: 7.6m; Green_REACh: Incomplete; Value: 470nH; Imax_A: 3.5A; SizeZ_mm: 1.6; SizeX_mm: 4.3; SizeArea_mm2: 18.49; AEC Category: Q200
Q5 = CMP-0000948-2: MOSFET, N-CH, 100 V, 0.17 A, SOT-323; Alternate Manufacturer: None; Manufacturer: Diodes Inc.; SizeZ_mm: 1.1; ChType: N; Value1: 1; VdsMax_V: 100V; SizeX_mm: 2.2; Vgs_V: 20V; Value: 100V; Rdson45_ohm: 10; SizeArea_mm2: 4.84; AEC Category: Q101; IdsMax_A: 1.7dA; SizeAreaWB_mm2: 10.24; U/M: EA
R19 = CMP-0026435-2: RES, 511 k, 1%, 0.063 W, AEC-Q200 Grade 0, 0402; Manufacturer: Vishay-Dale; Power_W: 63mW; TempCo: 100 ppm/C; Value: 511k; EIA_Code: E96; SizeX_mm: 1; SizeY_mm: 0.5; SizeZ_mm: 0.6; Value2: 0.063W; AEC Qualified: Y; VDC_V: 50V; AEC Category: Q200; AEC Grade: 0
R20 = CMP-0026158-2: RES, 200 k, 1%, 0.063 W, AEC-Q200 Grade 0, 0402; Manufacturer: Vishay-Dale; Power_W: 63mW; TempCo: 100 ppm/C; Value: 200k; EIA_Code: E96; SizeX_mm: 1; SizeY_mm: 0.5; SizeZ_mm: 0.6; Value2: 0.063W; AEC Qualified: Y; VDC_V: 50V; AEC Category: Q200; AEC Grade: 0
R21 R49 = CMP-0094182-1: 100 kOhms ±5% 0.063W, 1/16W Chip Resistor 0402 (1005 Metric) Moisture Resistant Thick Film; Part Number: RC0402JR-07100KL; Manufacturer: YAGEO; Power_W: 63mW; AEC Qualified: No; TempCo: 100ppm/°C; VDC_V: 50V; SizeZ_mm: 0.4mm
R22 = CMP-0080879-1: RES, 91.0 k, 1%, 0.063 W, 1x0.5mm; Manufacturer: Yageo America; Value_Code: 91k0; SizeAreaWB_mm2: 3; SizeArea_mm2: 0.5; AEC Qualified: N; AEC Category: Q200; Res_ohm: 91k; Value: 91.0k; SizeZ_mm: 0.4; TempCo: 100 ppm/C; Power_W: 63mW; VDC_V: 50V; Value2: 0.063W; SizeX_mm: 1
R23 R24 = CMP-0078212-1: RES, 510, 5%, 0.1 W, AEC-Q200 Grade 0, 0402; Manufacturer: Panasonic; Value_Code: 510R; SizeArea_mm2: 0.5; AEC Qualified: Y; AEC Category: Q200; Value: 510; SizeZ_mm: 0.6; EIA_Code: E24; TempCo: 200 ppm/C; AEC Grade: 0; Power_W: 100mW; VDC_V: 50V; Value2: 0.1W; U/M: EA; SizeX_mm: 1
R53 = CMP-0026757-1: RES, 1.00 M, 1%, 0.063 W, AEC-Q200 Grade 0, 0402; Manufacturer: Stackpole Electronics Inc; Power_W: 63mW; TempCo: 100 ppm/C; Value_Code: 1M00; U/M: EA; Value: 1.00Meg; EIA_Code: E96; Res_ohm: 1M; SizeX_mm: 1; SizeY_mm: 0.5; SizeZ_mm: 0.6; Value2: 0.063W; AEC Qualified: Y; VDC_V: 50V; AEC Grade: 0; AEC Category: Q200
SW1 = CMP-0087382-1: Dip Switch SPST 1 Position Through Hole Slide (Standard) Actuator 25mA 24VDC; Manufacturer: Wurth; Symbol Name: SYM-418117270901; VDC_V: 24V; SizeZ_mm: 6.95mm; PositionCount: 1
TP1 TP2 = CMP-0078143-4: TEST POINT.  No entry in BOM.
U3 = CMP-0086313-1: 2 A, High-Efficient, Low IQ Buck- Boost Converter with Small Solution Size, YFF0015AHAN (DSBGA-15); Alternate Manufacturer: Texas Instruments; SizeArea_mm2: 3.1625; SizeAreaWB_mm2: 7.8375; SizeY_mm: 2.3; SizeZ_mm: 0.625; AEC Qualified: N; CompType: IC; SizeX_mm: 1.375; AEC Category: Q200

## Sheet TIDA_010254_Base_Board_CC1352R.SchDoc: CC1352R_CHIP
size 431 x 279 mm; Date: Not shown in title block; ApprovedBy: Not shown in title block; CheckedBy: Not shown in title block; Author: Not shown in title block; CompanyName: Not shown in title block; DrawnBy: Justin Yin; Engineer: Not shown in title block; Organization: Not shown in title block; Address1: Not shown in title block; Address2: Not shown in title block; Address3: Not shown in title block; Address4: Not shown in title block; DocumentNumber: 6; Revision: Use project parameter SCH_Rev; SheetNumber: 6; SheetTotal: 8; PageSetup: Record=PageOptions¦CenterHorizontal=True¦CenterVertical=True¦PrintScale=1.00¦XCorrection=1.00¦YCorrection=1.00¦PrintKind=0¦BorderSize=5000000¦LeftOffset=0¦BottomOffset=0¦Orientation=2¦PaperLength=1000¦PaperWidth=1000¦Scale=100¦PaperSource=15¦PrintQuality=600¦MediaType=1¦DitherType=10¦PaperKind=Letter¦PrintScaleMode=1
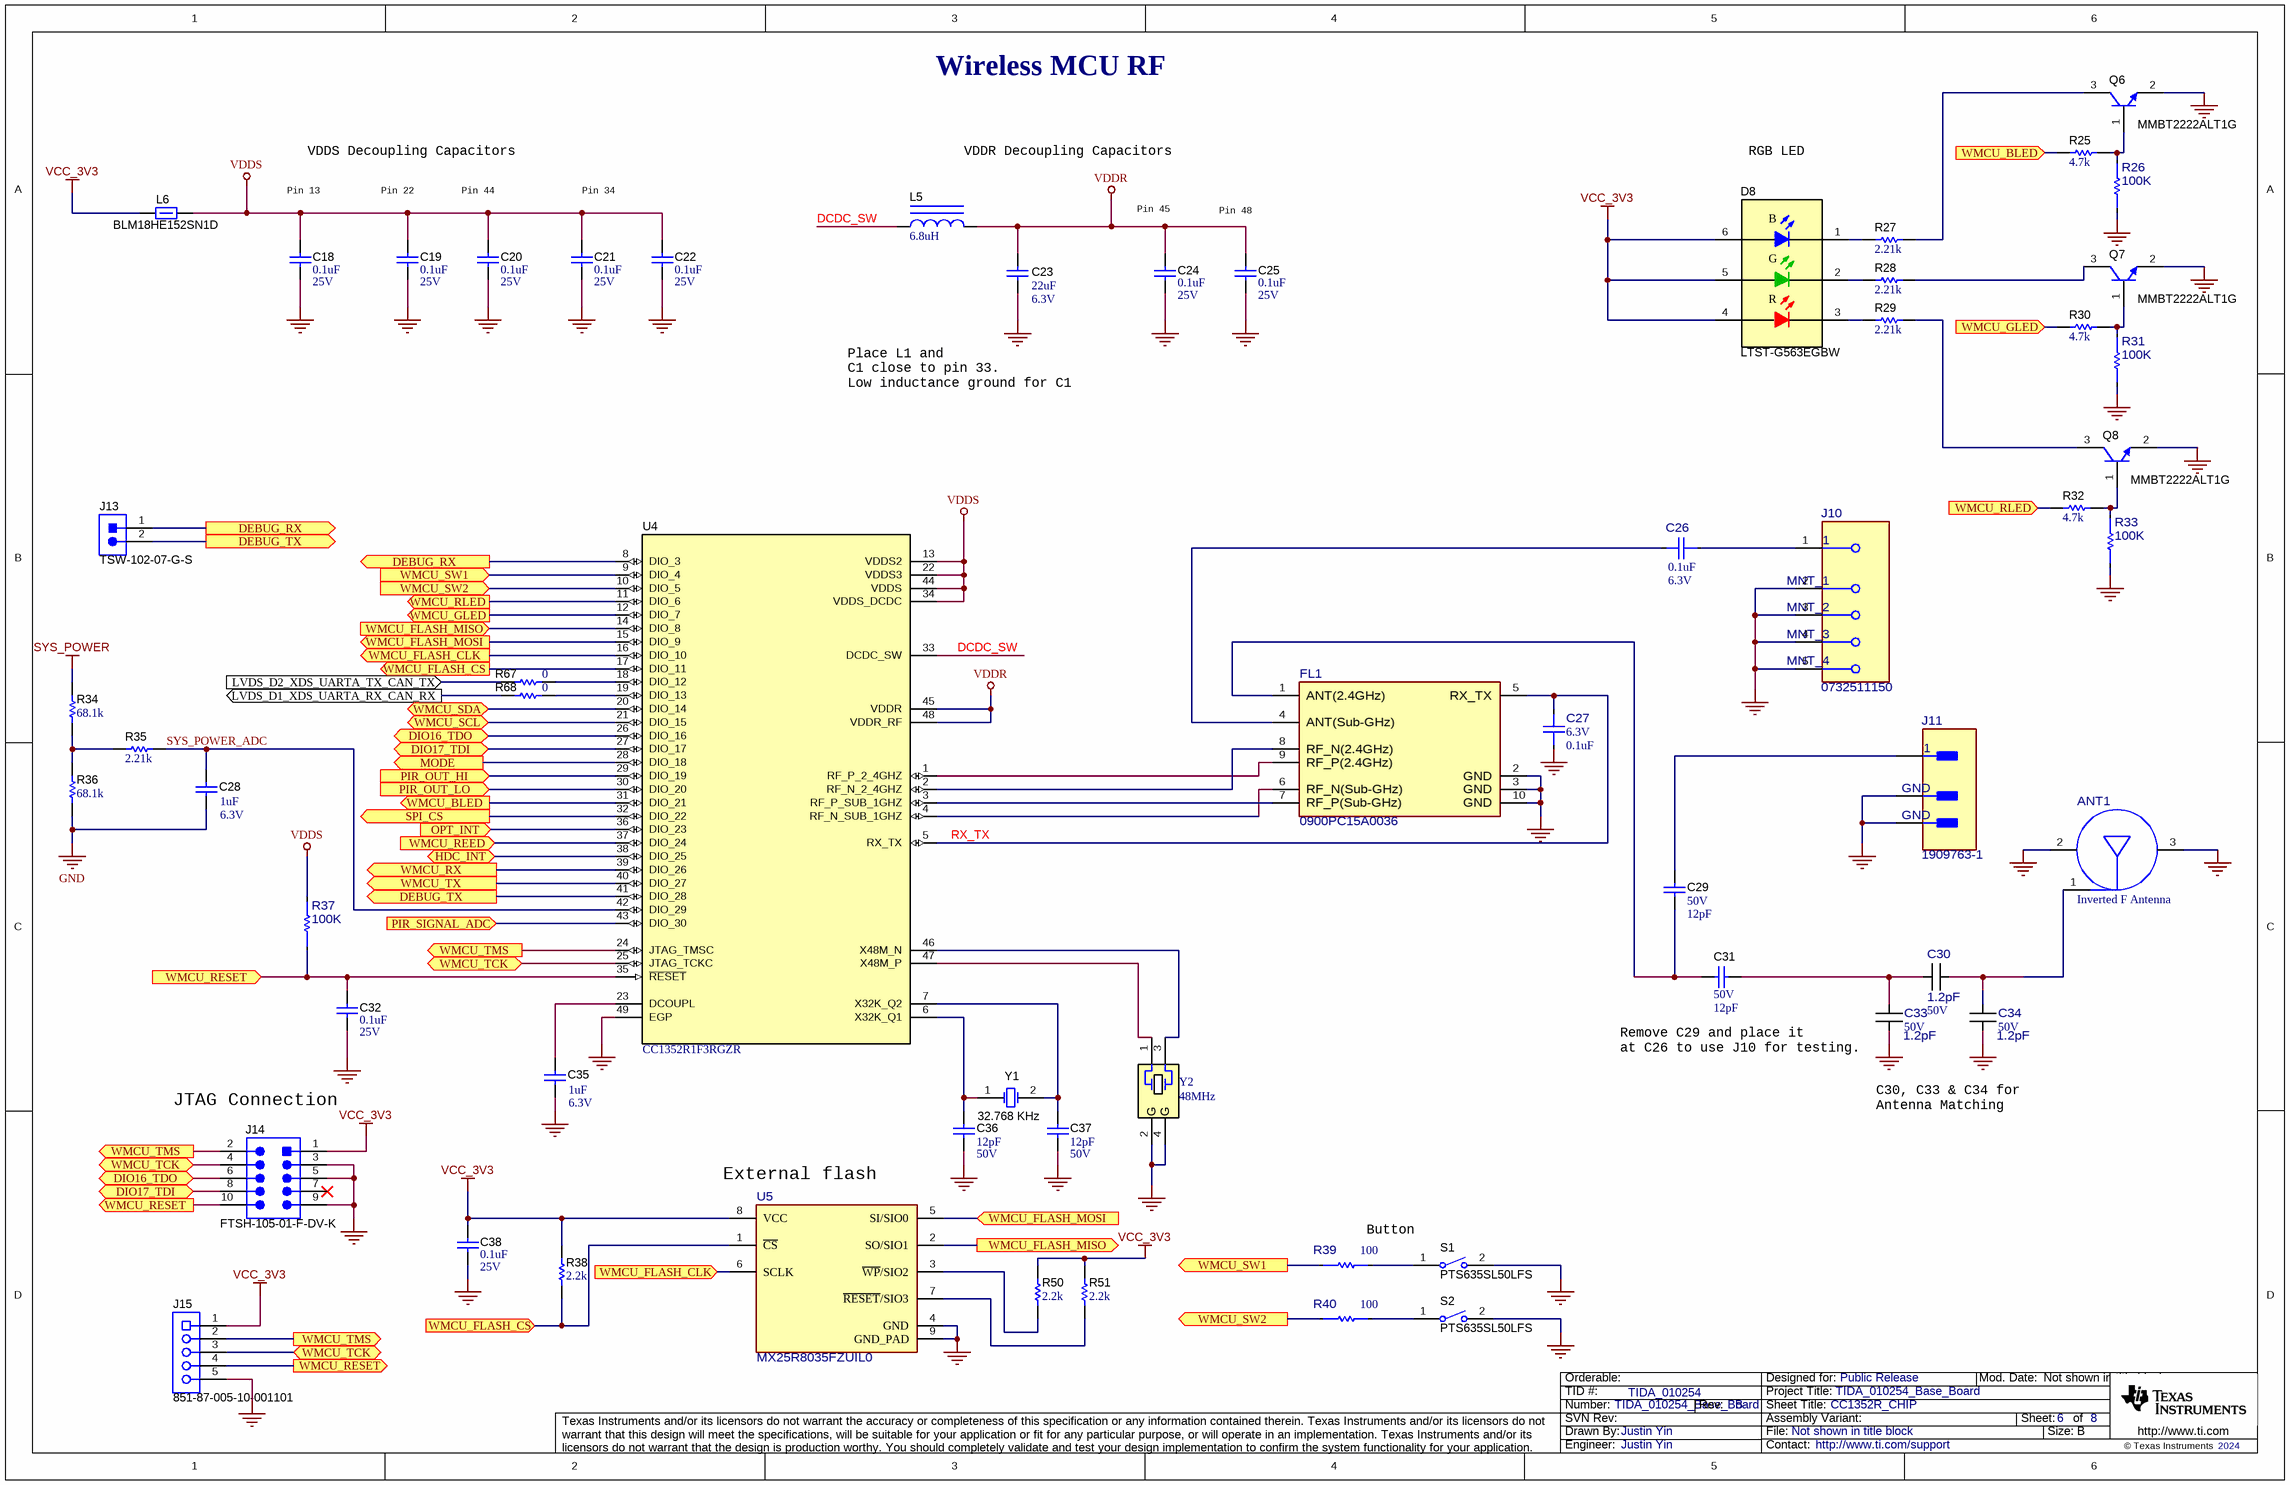
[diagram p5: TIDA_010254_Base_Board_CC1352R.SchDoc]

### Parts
ANT1  Inverted F Antenna  [0-MFG]
C18  VDC_V: 25V  ValueDisplayed: 0.1uF  [0402]  (hidden comment: GRM155R71E104KE14D)
C19  VDC_V: 25V  ValueDisplayed: 0.1uF  [0402]  (hidden comment: GRM155R71E104KE14D)
C20  VDC_V: 25V  ValueDisplayed: 0.1uF  [0402]  (hidden comment: GRM155R71E104KE14D)
C21  VDC_V: 25V  ValueDisplayed: 0.1uF  [0402]  (hidden comment: GRM155R71E104KE14D)
C22  VDC_V: 25V  ValueDisplayed: 0.1uF  [0402]  (hidden comment: GRM155R71E104KE14D)
C23  VDC_V: 6.3V  ValueDisplayed: 22uF  [0603]  (hidden comment: GRM188R60J226MEA0D)
C24  VDC_V: 25V  ValueDisplayed: 0.1uF  [0402]  (hidden comment: GRM155R71E104KE14D)
C25  VDC_V: 25V  ValueDisplayed: 0.1uF  [0402]  (hidden comment: GRM155R71E104KE14D)
C26  VDC_V: 6.3V  ValueDisplayed: 0.1uF  [FP-GRM033R60J104KE19D_0201-MFG]  (hidden comment: GRM033R60J104KE19D)
C27  VDC_V: 6.3V  ValueDisplayed: 0.1uF  [FP-GRM033R60J104KE19D_0201-MFG]  (hidden comment: GRM033R60J104KE19D)
C28  VDC_V: 6.3V  ValueDisplayed: 1uF  [0402]  (hidden comment: GRM155R70J105KA12D)
C29  VDC_V: 50V  ValueDisplayed: 12pF  [0201]  (hidden comment: GRM0335C1H120JA01D)
C30  1.2pF  VDC_V: 50V  [FP-GRM0335C1H1R2BA01D_0201-MFG]
C31  VDC_V: 50V  ValueDisplayed: 12pF  [0201]  (hidden comment: GRM0335C1H120JA01D)
C32  VDC_V: 25V  ValueDisplayed: 0.1uF  [0402]  (hidden comment: GRM155R71E104KE14D)
C33  1.2pF  VDC_V: 50V  [FP-GRM0335C1H1R2BA01D_0201-MFG]
C34  1.2pF  VDC_V: 50V  [FP-GRM0335C1H1R2BA01D_0201-MFG]
C35  VDC_V: 6.3V  ValueDisplayed: 1uF  [0402]  (hidden comment: GRM155R70J105KA12D)
C36  VDC_V: 50V  ValueDisplayed: 12pF  [0201]  (hidden comment: GRM0335C1H120JA01D)
C37  VDC_V: 50V  ValueDisplayed: 12pF  [0201]  (hidden comment: GRM0335C1H120JA01D)
C38  VDC_V: 25V  ValueDisplayed: 0.1uF  [0402]  (hidden comment: GRM155R71E104KE14D)
D8  LTST-G563EGBW  [G563EGBW]
FL1  0900PC15A0036  [FP-0900PC15A0036_0805-MFG]
J10  0732511150  [FP-0732511150_CONN_RF_JACK-MFG]
J11  1909763-1  [FP-1909763-1_SMT_JACK _CONN-MFG]
J13  TSW-102-07-G-S  [TSW-102-07-G-S]
J14  FTSH-105-01-F-DV-K  [Samtec_FTSH-105-01-x-DV-K]
J15  851-87-005-10-001101  [PRECI-DIP_851-87-005-10-001101]
L5  ValueDisplayed: 6.8uH  [0805_HV]  (hidden comment: MLZ2012N6R8LT000)
L6  BLM18HE152SN1D  [0603]
Q6  MMBT2222ALT1G  [SOT-23]
Q7  MMBT2222ALT1G  [SOT-23]
Q8  MMBT2222ALT1G  [SOT-23]
R25  ValueDisplayed: 4.7k  [0402]  (hidden comment: CRCW04024K70JNED)
R26  100K  [FP-RC0402JR-07100KL_0402-MFG]
R27  ValueDisplayed: 2.21k  [0402]  (hidden comment: CRCW04022K21FKED)
R28  ValueDisplayed: 2.21k  [0402]  (hidden comment: CRCW04022K21FKED)
R29  ValueDisplayed: 2.21k  [0402]  (hidden comment: CRCW04022K21FKED)
R30  ValueDisplayed: 4.7k  [0402]  (hidden comment: CRCW04024K70JNED)
R31  100K  [FP-RC0402JR-07100KL_0402-MFG]
R32  ValueDisplayed: 4.7k  [0402]  (hidden comment: CRCW04024K70JNED)
R33  100K  [FP-RC0402JR-07100KL_0402-MFG]
R34  ValueDisplayed: 68.1k  [0402S]  (hidden comment: CRCW040268K1FKED)
R35  ValueDisplayed: 2.21k  [0402]  (hidden comment: CRCW04022K21FKED)
R36  ValueDisplayed: 68.1k  [0402S]  (hidden comment: CRCW040268K1FKED)
R37  100K  [FP-RC0402JR-07100KL_0402-MFG]
R38  ValueDisplayed: 2.2k  [0402]  (hidden comment: CRCW04022K20JNED)
R39  value 100  [FP-RC0402JR-13100RL_0402-MFG]  (hidden comment: RC0402JR-13100RL)
R40  value 100  [FP-RC0402JR-13100RL_0402-MFG]  (hidden comment: RC0402JR-13100RL)
R50  ValueDisplayed: 2.2k  [0402]  (hidden comment: CRCW04022K20JNED)
R51  ValueDisplayed: 2.2k  [0402]  (hidden comment: CRCW04022K20JNED)
R67  ValueDisplayed: 0  [0402]  (hidden comment: RC0402JR-070RL)
R68  ValueDisplayed: 0  [0402]  (hidden comment: RC0402JR-070RL)
S1  PTS635SL50LFS  [SW_PTS635SL50]
S2  PTS635SL50LFS  [SW_PTS635SL50]
U4  CC1352R1F3RGZR  [RGZ0048A]
U5  MX25R8035FZUIL0  [FP-MX25R8035FZUIL0_USON8-0]
Y1  32.768 KHz  [Epson_FC-135]
Y2  Frequency_Fixed: 48MHz  [Kyocera_CX2016DB]  (hidden comment: CX2016DB48000C0FPLC1)

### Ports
DEBUG_RX (out), DEBUG_TX (out), DIO16_TDO (bidir), DIO17_TDI (bidir), HDC_INT (bidir), LVDS_D1_XDS_UARTA_RX_CAN_RX (out), LVDS_D2_XDS_UARTA_TX_CAN_TX (in), MODE (out), OPT_INT (in), PIR_OUT_HI (in), PIR_OUT_LO (in), PIR_SIGNAL_ADC (in), SPI_CS (out), WMCU_BLED (in), WMCU_BLED (out), WMCU_FLASH_CLK (in), WMCU_FLASH_CLK (out), WMCU_FLASH_CS (in), WMCU_FLASH_CS (out), WMCU_FLASH_MISO (in), WMCU_FLASH_MISO (out), WMCU_FLASH_MOSI (in), WMCU_FLASH_MOSI (out), WMCU_GLED (in), WMCU_GLED (out), WMCU_REED (in), WMCU_RESET (in), WMCU_RESET (out), WMCU_RLED (in), WMCU_RLED (out), WMCU_RX (out), WMCU_SCL (bidir), WMCU_SDA (bidir), WMCU_SW1 (in), WMCU_SW1 (out), WMCU_SW2 (in), WMCU_SW2 (out), WMCU_TCK (bidir), WMCU_TMS (out), WMCU_TX (out)

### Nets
GND: ANT1.2(GND) ANT1.3(GND) C18.2 C19.2 C20.2 C21.2 C22.2 C23.2 C24.2 C25.2 C27.1 C28.2 C32.2 C33.2 C34.2 C35.2 C36.2 C37.2 C38.2 FL1.2(GND) FL1.3(GND) FL1.10(GND) J10.2(MNT_1) J10.3(MNT_2) J10.4(MNT_3) J10.5(MNT_4) J11.2(GND) J11.3(GND) J14.3 J14.5 J14.9 J15.5 Q6.2(E) Q7.2(E) Q8.2(E) R26.2 R31.2 R33.2 R36.1 S1.2 S2.2 U4.49(EGP) U5.4(GND) U5.9(GND_PAD) Y2.2(GND) Y2.4(GND)
SYS_POWER: R34.2
VCC_3V3: C38.1 D8.4(A) D8.5(A) D8.6(A) J14.1 J15.1 L6.1 R38.2 R50.2 R51.2 U5.8(VCC)
VDDR: C23.1 C24.1 C25.1 L5.2 U4.45(VDDR) U4.48(VDDR_RF)
VDDS: C18.1 C19.1 C20.1 C21.1 C22.1 L6.2 R37.2 U4.13(VDDS2) U4.22(VDDS3) U4.34(VDDS_DCDC) U4.44(VDDS)
DCDC_SW: L5.1 U4.33(DCDC_SW)
DEBUG_RX: J13.1 U4.8(DIO_3) ; port DEBUG_RX
DEBUG_TX: J13.2 U4.41(DIO_28) ; port DEBUG_TX
DIO16_TDO: J14.6 U4.26(DIO_16) ; port DIO16_TDO
DIO17_TDI: J14.8 U4.27(DIO_17) ; port DIO17_TDI
HDC_INT: U4.38(DIO_25) ; port HDC_INT
LVDS_D1_XDS_UARTA_RX_CAN_RX: R68.1 ; port LVDS_D1_XDS_UARTA_RX_CAN_RX
LVDS_D2_XDS_UARTA_TX_CAN_TX: R67.1 ; port LVDS_D2_XDS_UARTA_TX_CAN_TX
MODE: U4.28(DIO_18) ; port MODE
OPT_INT: U4.36(DIO_23) ; port OPT_INT
PIR_OUT_HI: U4.29(DIO_19) ; port PIR_OUT_HI
PIR_OUT_LO: U4.30(DIO_20) ; port PIR_OUT_LO
PIR_SIGNAL_ADC: U4.43(DIO_30) ; port PIR_SIGNAL_ADC
RX_TX: C27.2 FL1.5(RX_TX) U4.5(RX_TX)
SPI_CS: U4.32(DIO_22) ; port SPI_CS
SYS_POWER_ADC: C28.1 R35.1 U4.42(DIO_29)
WMCU_BLED: R25.1 U4.31(DIO_21) ; port WMCU_BLED
WMCU_FLASH_CLK: U4.16(DIO_10) U5.6(SCLK) ; port WMCU_FLASH_CLK
WMCU_FLASH_CS: R38.1 U4.17(DIO_11) U5.1(~{CS}) ; port WMCU_FLASH_CS
WMCU_FLASH_MISO: U4.14(DIO_8) U5.2(SO/SIO1) ; port WMCU_FLASH_MISO
WMCU_FLASH_MOSI: U4.15(DIO_9) U5.5(SI/SIO0) ; port WMCU_FLASH_MOSI
WMCU_GLED: R30.1 U4.12(DIO_7) ; port WMCU_GLED
WMCU_REED: U4.37(DIO_24) ; port WMCU_REED
WMCU_RESET: C32.1 J14.10 J15.4 R37.1 U4.35(~{RESET}) ; port WMCU_RESET
WMCU_RLED: R32.1 U4.11(DIO_6) ; port WMCU_RLED
WMCU_RX: U4.39(DIO_26) ; port WMCU_RX
WMCU_SCL: U4.21(DIO_15) ; port WMCU_SCL
WMCU_SDA: U4.20(DIO_14) ; port WMCU_SDA
WMCU_SW1: R39.1 U4.9(DIO_4) ; port WMCU_SW1
WMCU_SW2: R40.1 U4.10(DIO_5) ; port WMCU_SW2
WMCU_TCK: J14.4 J15.3 U4.25(JTAG_TCKC) ; port WMCU_TCK
WMCU_TMS: J14.2 J15.2 U4.24(JTAG_TMSC) ; port WMCU_TMS
WMCU_TX: U4.40(DIO_27) ; port WMCU_TX
NetANT1_1: ANT1.1(Feed) C30.2 C34.1
NetC26_1: C26.1 J10.1
NetC26_2: C26.2 FL1.4(ANT(Sub-GHz))
NetC29_1: C29.1 J11.1
NetC29_2: C29.2 C31.1 FL1.1(ANT(2.4GHz))
NetC30_1: C30.1 C31.2 C33.1
NetC35_1: C35.1 U4.23(DCOUPL)
NetC36_1: C36.1 U4.6(X32K_Q1) Y1.1(OSC1)
NetC37_1: C37.1 U4.7(X32K_Q2) Y1.2(OSC2)
NetD8_1: D8.1(K) R27.2
NetD8_2: D8.2(K) R28.2
NetD8_3: D8.3(K) R29.2
NetFL1_6: FL1.6(RF_N(Sub-GHz)) U4.4(RF_N_SUB_1GHZ)
NetFL1_7: FL1.7(RF_P(Sub-GHz)) U4.3(RF_P_SUB_1GHZ)
NetFL1_8: FL1.8(RF_N(2.4GHz)) U4.2(RF_N_2_4GHZ)
NetFL1_9: FL1.9(RF_P(2.4GHz)) U4.1(RF_P_2_4GHZ)
NetQ6_1: Q6.1(B) R25.2 R26.1
NetQ6_3: Q6.3(C) R27.1
NetQ7_1: Q7.1(B) R30.2 R31.1
NetQ7_3: Q7.3(C) R28.1
NetQ8_1: Q8.1(B) R32.2 R33.1
NetQ8_3: Q8.3(C) R29.1
NetR34_1: R34.1 R35.2 R36.2
NetR39_2: R39.2 S1.1
NetR40_2: R40.2 S2.1
NetR50_1: R50.1 U5.3(~{WP}/SIO2)
NetR51_1: R51.1 U5.7(~{RESET}/SIO3)
NetR67_2: R67.2 U4.18(DIO_12)
NetR68_2: R68.2 U4.19(DIO_13)
NetU4_46: U4.46(X48M_N) Y2.3
NetU4_47: U4.47(X48M_P) Y2.1

Not connected (* = marked no-connect by the designer): J14 7*

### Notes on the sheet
- Wireless MCU RF
- VDDS Decoupling Capacitors
- VDDR Decoupling Capacitors
- RGB LED
- Pin 13
- Pin 22
- Pin 44
- Pin 34
- (near C24) Pin 45
- Pin 48
- Place L1 and
  C1 close to pin 33.
  Low inductance ground for C1
- (near J14) JTAG Connection
- Remove C29 and place it
  at C26 to use J10 for testing.
- C30, C33 & C34 for
  Antenna Matching
- (near U5) External flash
- Button

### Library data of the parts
ANT1 = CMP-0091830-1: 2.4-GHz Inverted F Antenna; Manufacturer: Texas Instruments; AEC Qualified: No; Number Of Bands: 1
C18-C22 C24 C25 C32 C38 = CMP-0006659-2: CAP, CERM, 0.1 uF, 25 V, +/- 10%, X7R, 0402; Manufacturer: MuRata; TaMin_C: -55°C; Polarized: N; SizeAreaWB_mm2: 3; Value1: Unknown; U/M: EA; Value: 0.1uF; TaMax_C: 125°C; SizeZ_mm: 0.6; SizeX_mm: 1; SizeY_mm: 0.5; Cap_F: 100nF; AEC Category: Q200
C23 = CMP-0007306-5: CAP, CERM, 22 uF, 6.3 V, +/- 20%, X5R, 0603; Manufacturer: MuRata; TaMin_C: -55°C; Polarized: N; SizeAreaWB_mm2: 4.68; Value1: Unknown; U/M: EA; Value: 22uF; TaMax_C: 85°C; SizeZ_mm: 1; SizeX_mm: 1.6; SizeY_mm: 0.8; SizeArea_mm2: 1.28; Cap_F: 22µF; AEC Category: Q200
C26 C27 = CMP-0088531-2: 0.1µF ±10% 6.3V Ceramic Capacitor X5R 0201 (0603 Metric); Manufacturer: Murata; AEC Qualified: No; SizeZ_mm: 0.33mm; TempCo: 15%; Cap_F: 100nF
C28 C35 = CMP-0064947-2: CAP, CERM, 1 uF, 6.3 V,+/- 10%, X7R, 0402; Manufacturer: MuRata; TaMin_C: -55°C; Polarized: N; SizeAreaWB_mm2: 3; Value1: Unknown; U/M: EA; Value: 1uF; TaMax_C: 125°C; SizeZ_mm: 0.6; SizeX_mm: 1; SizeY_mm: 0.5; Cap_F: 1µF; AEC Category: Q200
C29 C31 C36 C37 = CMP-0009664-3: CAP, CERM, 12 pF, 50 V, +/- 5%, C0G/NP0, 0201; Manufacturer: MuRata; TaMin_C: -55°C; Polarized: N; SizeAreaWB_mm2: 2.08; Value1: Unknown; U/M: EA; Value: 12pF; TaMax_C: 125°C; SizeZ_mm: 0.26; SizeY_mm: 0.3; SizeArea_mm2: 0.18; SizeX_mm: 0.6; AEC Category: Q200
C30 C33 C34 = CMP-0086449-1: Multilayer Ceramic Capacitors MLCC - SMD/SMT 0201 1.2pF 50volts C0G +/-0.1pF; PartNumber: GRM0335C1H1R2BA01D; Manufacturer: Murata Electronics North America; TempCo: 30ppm/°C; SizeZ_mm: 0.33mm; Symbol Name: SYM-GRM0335C1H1R2BA01D; AEC Qualified: No
D8 = CMP-0085925-1: LED, RGB, SMD; Manufacturer: Lite-On; Power_TotalModule: 130mW; SizeZ_mm: 1.8; Angle: 120; Io_A: 20mA; SizeY_mm: 5; Tjmax_C: 85°C; SizeAreaWB_mm2: 51.8; Value2: 3.8V; SizeX_mm: 5.4; SizeArea_mm2: 27; Vr_V: 5V; Ir_A: 10µA; Value1: 0.13W
FL1 = CMP-0088981-1: RF Balun 862MHz ~ 928MHz, 2.4GHz ~ 2.5GHz 50 / 50Ohm 0805 (2012 Metric), 10 PC Pad; Manufacturer: Johanson Technology; Bandwidth: 862-928/2400-2500MHz; AEC Qualified: No; Insertion Loss: 1.8/1.3dB; SizeZ_mm: 1mm
J10 = CMP-0087962-2: SMA Connector Receptacle, Female Socket 50Ohm Board Edge, End Launch Solder; Manufacturer: Molex Inc
J11 = CMP-0091846-1: U.FL (UMCC) Connector Jack, Male Pin 50Ohm Surface Mount Solder; Manufacturer: TE Connectivity; Conn Orientation: Vertical; AEC Qualified: No; SizeZ_mm: 1.5mm; Impedance: 50Ω; Frequency_Fixed: 0-6GHz; ContactFinish: Gold,Nickel; Dielectric Material: Liquid Crystal Polymer
J13 = CMP-0075405-3: as J3 on sheet TIDA_010254_Base_Board_Connector
J14 = CMP-0075670-2: Header (Shrouded), 1.27mm, 5x2, Gold, SMT; Manufacturer: Samtec; Pitch_mm: 1.27; Gender: Male; Cert_CSA: Y; Current_A: 3.3A; Row_Count: 2
J15 = CMP-0074998-1: Receptacle, 5x1, 1.27mm, TH; Manufacturer: Preci-Dip; CT: False; CompType: Socket
L5 = CMP-0062727-1: Inductor, Multilayer, Ferrite, 6.8 uH, 0.11 A, 0.25 ohm, SMD; Manufacturer: TDK; Isat: 0.11A @ 50% inductance drop; Irms: 0.55A @ 20C rise; Green_Lifecycle: Active; SizeAreaWB_mm2: 6.75; DCR_ohm: 2.5d; Green_REACh: Passed; Value: 6.8uH; Imax_A: 1.1dA; SizeZ_mm: 1.45; SizeX_mm: 2; SizeY_mm: 1.25; Value2: 0.11A; SizeArea_mm2: 2.5; Ind_H: 6.8µH; AEC Category: Q200
L6 = CMP-0003349-2: Ferrite Bead, 1500 ohm @ 100 MHz, 0.5 A, 0603; Manufacturer: MuRata; Ztyp@1GHz_Ohm: 1.5k; SizeAreaWB_mm2: 4.68; DCR_ohm: 5d; Value1: 0.5 ohm; Imax_A: 5dA; SizeZ_mm: 1; SizeX_mm: 1.6; SizeY_mm: 0.8; Value2: 0.5A; SizeArea_mm2: 1.28
Q6-Q8 = CMP-0000461-2: Transistor, NPN, 40 V, 0.6 A, SOT-23; Manufacturer: ON Semiconductor; TaMax_C: 150°C; Value1: 0.6 A; Vcesat1_V: 1V; SizeX_mm: 2.5; SizeY_mm: 3; TaMin_C: -55°C; IcRated_A: 6dA; CompType: BJT; SizeZ_mm: 1.1; Value: 40 V; SizeArea_mm2: 7.5; NPN: 1; Vceo_V: 40V; PNP: 0; AEC Category: Q101; SizeAreaWB_mm2: 14; U/M: EA
R25 R30 R32 = CMP-0026938-5: RES, 4.7 k, 5%, 0.063 W, AEC-Q200 Grade 0, 0402; Manufacturer: Vishay-Dale; Power_W: 63mW; TempCo: 200 ppm/C; Value_Code: 4k70; Value: 4.7k; EIA_Code: E24; SizeX_mm: 1; SizeY_mm: 0.5; SizeZ_mm: 0.6; Value2: 0.063W; AEC Qualified: Y; VDC_V: 50V; AEC Category: Q200; AEC Grade: 0
R26 R31 R33 R37 = CMP-0094182-1: as R21 on sheet TIDA_010254_Base_Board_DC_Regulators
R27-R29 R35 = CMP-0026232-2: as R7 on sheet TIDA_010254_Base_Board_Charger
R34 R36 = CMP-0026506-2: RES, 68.1 k, 1%, 0.063 W, AEC-Q200 Grade 0, 0402; Manufacturer: Vishay-Dale; Power_W: 63mW; TempCo: 100 ppm/C; Value_Code: 68k1; Value: 68.1k; EIA_Code: E96; SizeX_mm: 1; SizeY_mm: 0.5; SizeZ_mm: 0.6; Value2: 0.063W; AEC Qualified: Y; VDC_V: 50V; AEC Category: Q200; AEC Grade: 0
R38 R50 R51 = CMP-0026890-5: RES, 2.2 k, 5%, 0.063 W, AEC-Q200 Grade 0, 0402; Manufacturer: Vishay-Dale; Power_W: 63mW; TempCo: 200 ppm/C; Value_Code: 2k20; Value: 2.2k; EIA_Code: E24; SizeX_mm: 1; SizeY_mm: 0.5; SizeZ_mm: 0.6; Value2: 0.063W; AEC Qualified: Y; VDC_V: 50V; AEC Category: Q200; AEC Grade: 0
R39 R40 = CMP-0092287-1: 100 ±5% 0.063W, 1/16W Chip Resistor 0402 (1005 Metric) Moisture Resistant Thick Film; Manufacturer: Yageo; Power_W: 63mW; TempCo: 100ppm/°C; AEC Qualified: No; SizeZ_mm: 0.4mm; VDC_V: 50V
R67 R68 = CMP-0027004-2: as R17 on sheet TIDA_010254_Base_Board_Connector
S1 S2 = CMP-0002133-2: Switch, Tactile, SPST-NO, 0.05A, 12V, TH; Manufacturer: C&K Components; CurrentRating_mA: 50A; PositionCount: 1; SwitchFunction: Off-Mom
U4 = CMP-0081246-4: SimpleLink High-Performance Dual-Band Wireless MCU, RGZ0048A (VQFN-48); Alternate PartNumber: CC1352R1F3RGZT; Alternate Manufacturer: Texas Instruments; AEC Category: Q200; CompType: IC; SizeAreaWB_mm2: 81; SizeArea_mm2: 49; AEC Qualified: N; SizeY_mm: 7; SizeZ_mm: 1
U5 = CMP-0086600-1: Ultra Low Power 8M-BIT [x 1/x 2/x 4] CMOS MXSMIO FLASH MEMORY; Manufacturer: Macronix International Co., Ltd.
Y1 = CMP-0079303-1: Crystal, 32.768 KHz, 20 ppm, 7 pF, SMD; Manufacturer: Epson; PartNumber: FC-135 32.7680KA-AG0; TaMin_C: -40°C; Frequency Tolerance: 20 ppm; Load Capacitance: 7 pF; TaMax_C: 85°C; AEC Qualified: N; AEC Category: Q200
Y2 = CMP-0081467-1: Crystal, 48 MHz, 10 ppm, 7 pF, SMD; Manufacturer: Kyocera; Frequency Stability: 20 ppm; SizeAreaWB_mm2: 7.8; SizeArea_mm2: 3.2; AEC Qualified: N; Frequency Tolerance: 10 ppm; AEC Category: Q200; TaMax_C: 85°C; SizeZ_mm: 0.45; TaMin_C: -40°C; SizeY_mm: 2; Load Capacitance: 7 pF; SizeX_mm: 1.6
